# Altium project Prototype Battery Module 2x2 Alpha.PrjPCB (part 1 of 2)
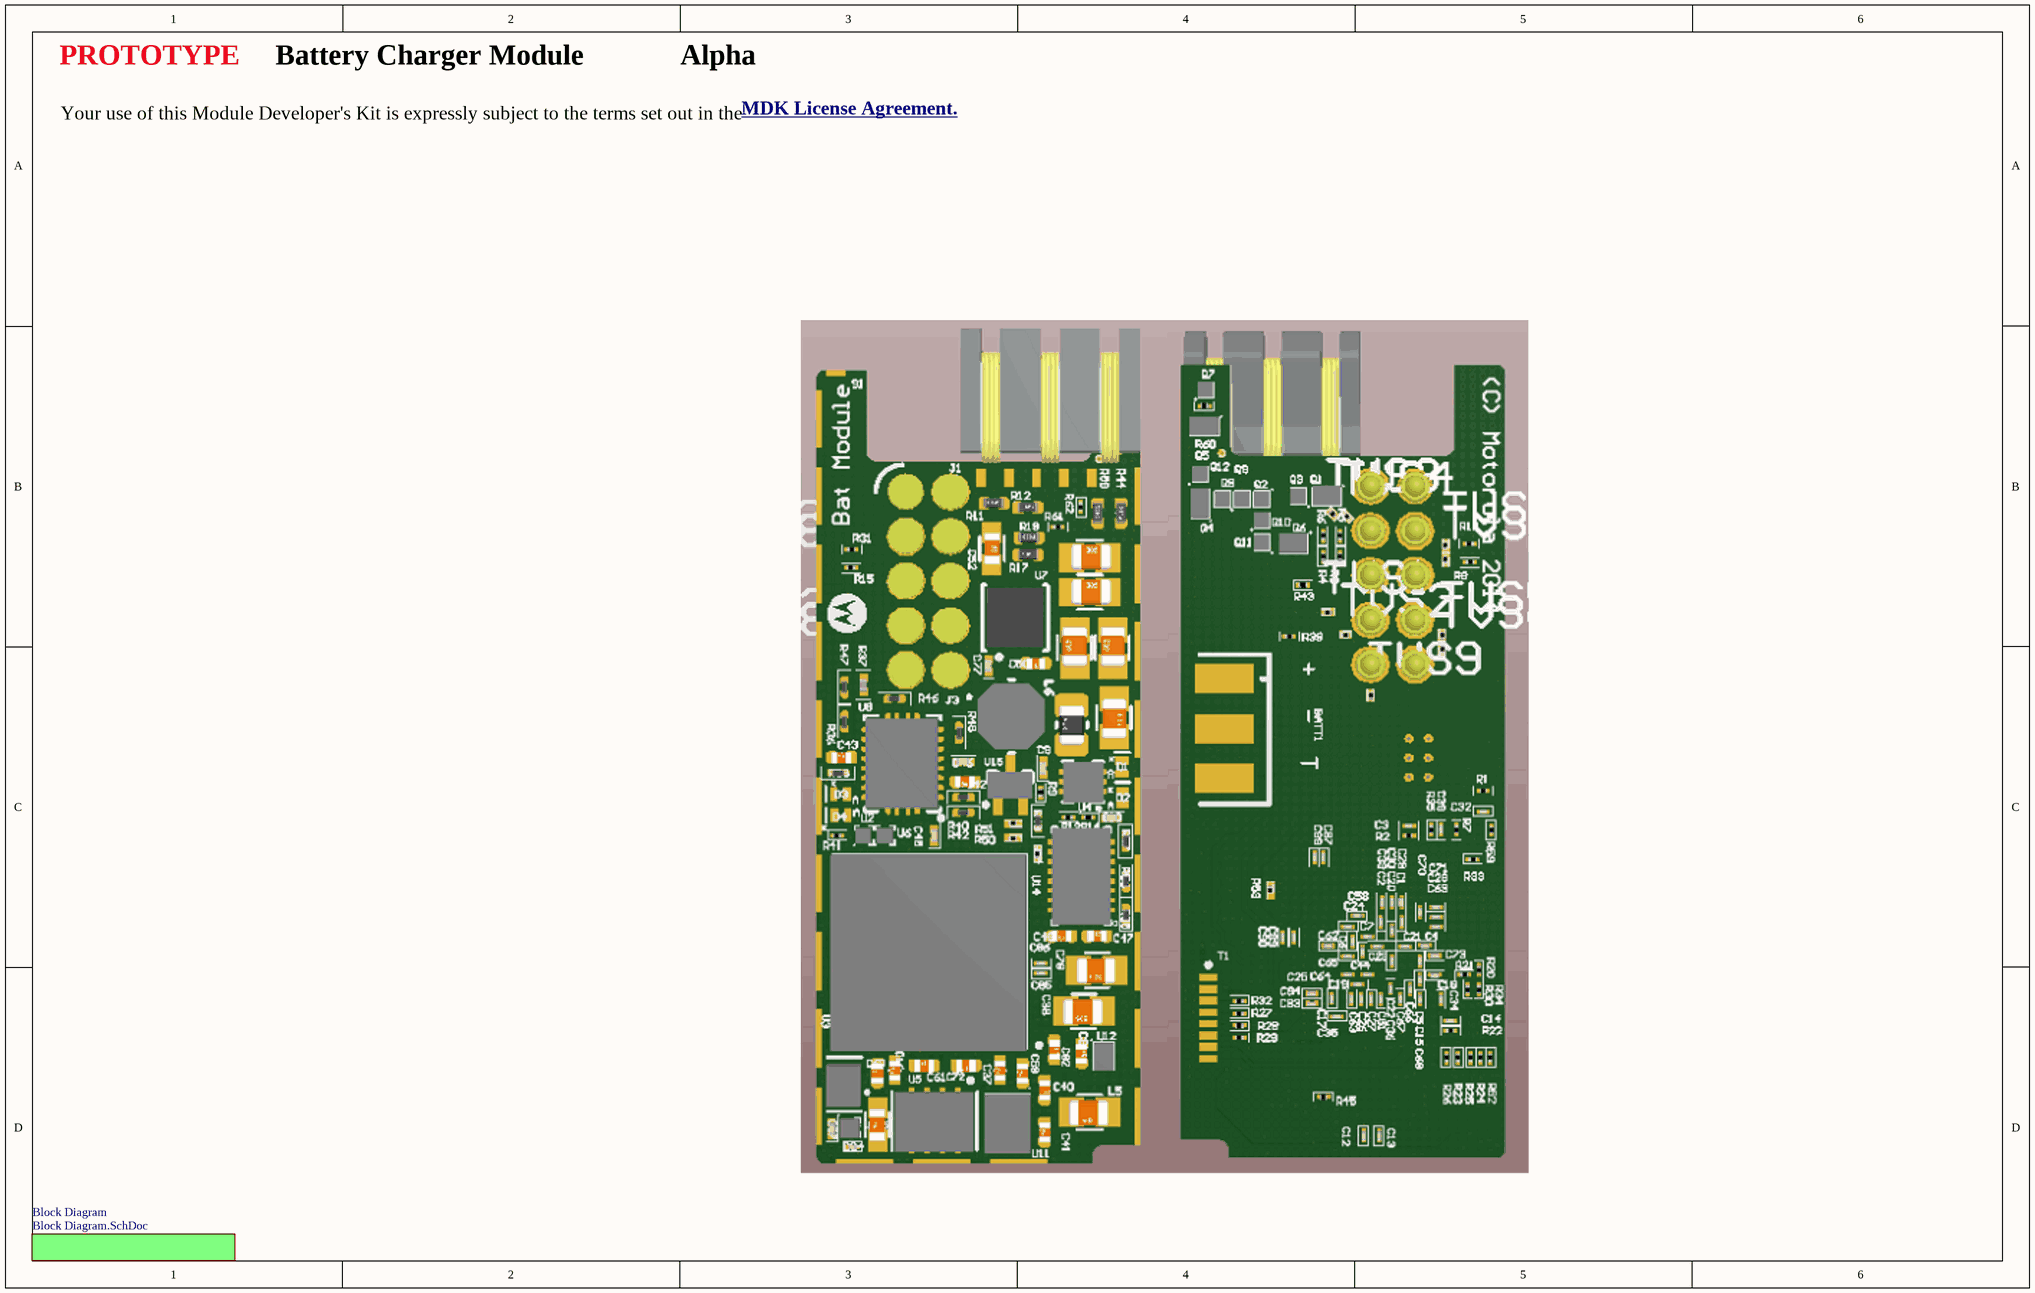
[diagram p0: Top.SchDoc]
Revision: C
12 sheets, 192 parts. Net scope: flat (ports and power ports of the same name join across sheets).
Board file: Prototype Battery Module 2x2 Alpha.PcbDoc
Sheets:
  Top.SchDoc
    Block Diagram = Block Diagram.SchDoc
      FPGA = FPGA.SchDoc
        Banks = FPGA Banks.SchDoc
        Config = FPGA Config.SchDoc
        Power = FPGA Power.SchDoc
        SERDES = FPGA SERDES.SchDoc
      Power = Power.SchDoc
      EPM = EPM.SchDoc
      HostComm = Host Comm.SchDoc
      Charger = Charger.SchDoc
      Ideal Diode = Ideal Diode.SchDoc

## Sheet Top.SchDoc: Top (License)
size B; Date: 3/12/2014; Engineer: David McCoy (Cospan Design); DocumentNumber: 1; Revision: A; SheetNumber: 1; SheetTotal: 13

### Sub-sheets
Block Diagram = Block Diagram.SchDoc: no entries

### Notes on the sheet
- PROTOTYPE
- Battery Charger Module
- Alpha
- Your use of this Module Developer's Kit is expressly subject to the terms set out in the
- MDK License Agreement. <http://www.projectara.com/mdk-license.txt>

## Sheet Block Diagram.SchDoc: Block Diagram
size B; Date: 12/18/2013; DrawnBy: David McCoy; Engineer: David McCoy (Cospan Design); DocumentNumber: 2; Revision: C; SheetNumber: 2; SheetTotal: 13
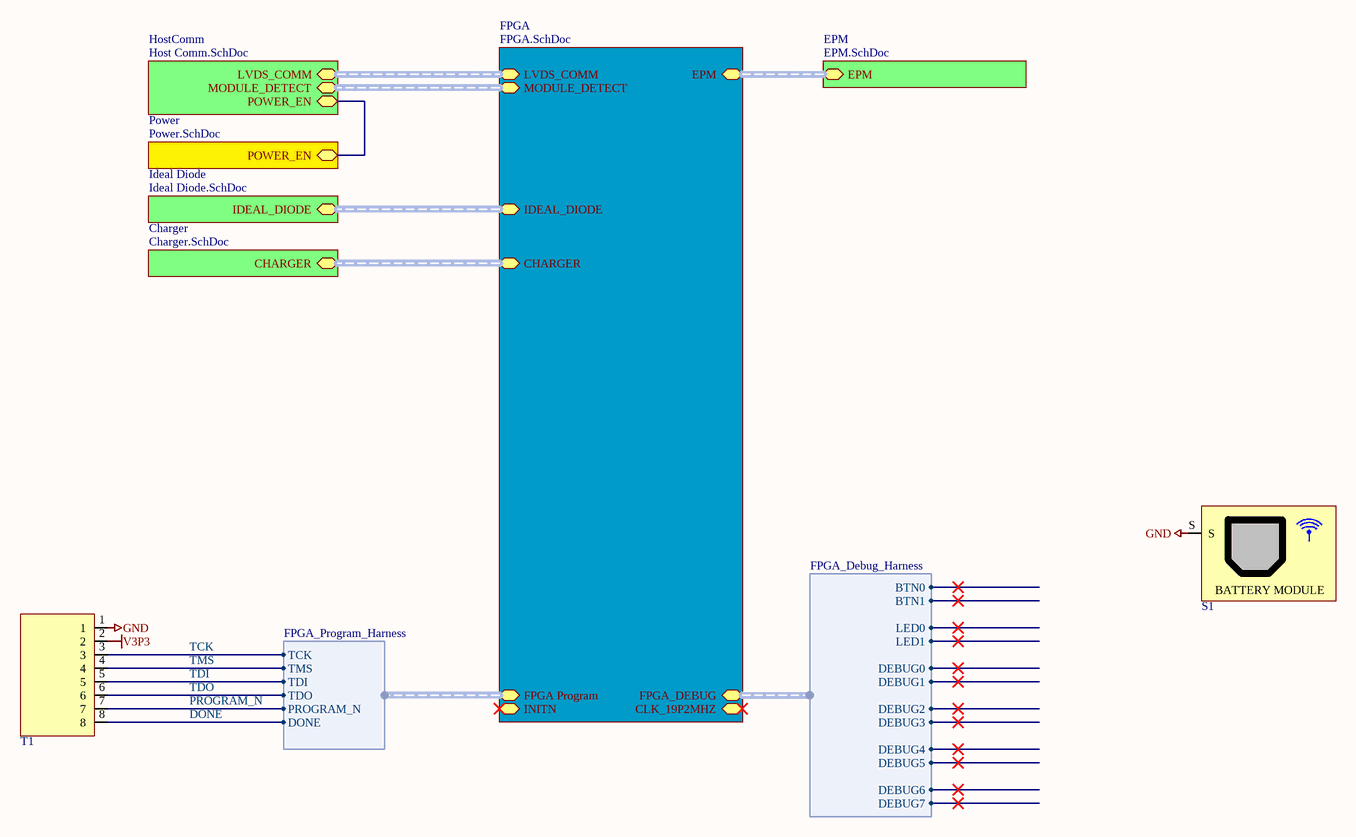
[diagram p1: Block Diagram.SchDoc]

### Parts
S1  RFSHIELD  [RFSHIELD_BATMODULE]  (value not drawn)  (no BOM)
T1  8 PIN TEST_INTERFACE  [8-PIN Test Interface]  (value not drawn)  (no BOM)

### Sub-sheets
Charger = Charger.SchDoc: CHARGER (harness Charger Harness)
EPM = EPM.SchDoc: EPM (harness EPM_Harness)
FPGA = FPGA.SchDoc: FPGA Program (harness FPGA_Program_Harness), INITN, FPGA_DEBUG (harness FPGA_Debug_Harness), CLK_19P2MHZ, EPM (harness EPM_Harness), LVDS_COMM (harness LVDS_Comm_Harness), MODULE_DETECT (harness Module_Detect_Harness), CHARGER (harness Charger Harness), IDEAL_DIODE (harness Ideal Diode Harness)
HostComm = Host Comm.SchDoc: LVDS_COMM (harness LVDS_Comm_Harness), MODULE_DETECT (harness Module_Detect_Harness), POWER_EN
Ideal Diode = Ideal Diode.SchDoc: IDEAL_DIODE (harness Ideal Diode Harness)
Power = Power.SchDoc: POWER_EN

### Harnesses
FPGA_Program_Harness: TCK, TMS, TDI, TDO, PROGRAM_N, DONE
FPGA_Debug_Harness: BTN0, BTN1, LED0, LED1, DEBUG0, DEBUG1, DEBUG2, DEBUG3, DEBUG4, DEBUG5, DEBUG6, DEBUG7

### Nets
GND: S1.S T1.1
V3P3: T1.2
DONE: T1.8 ; sheet FPGA/FPGA Program.DONE
PROGRAM_N: T1.7 ; sheet FPGA/FPGA Program.PROGRAM_N
TCK: T1.3 ; sheet FPGA/FPGA Program.TCK
TDI: T1.5 ; sheet FPGA/FPGA Program.TDI
TDO: T1.6 ; sheet FPGA/FPGA Program.TDO
TMS: T1.4 ; sheet FPGA/FPGA Program.TMS
(unnamed): sheet Power/POWER_EN, sheet HostComm/POWER_EN

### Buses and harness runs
harness sheet Charger/CHARGER = sheet FPGA/CHARGER
harness sheet EPM/EPM = sheet FPGA/EPM
harness sheet FPGA/IDEAL_DIODE = sheet Ideal Diode/IDEAL_DIODE
harness sheet FPGA/LVDS_COMM = sheet HostComm/LVDS_COMM
harness sheet FPGA/MODULE_DETECT = sheet HostComm/MODULE_DETECT

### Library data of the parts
S1 = S_RF_SHIELD_BATMODULE
T1 = TEST_INTERFACE: 8 PIN Test Interface

## Sheet FPGA.SchDoc: FPGA
size B; Date: 12/18/2013; DrawnBy: David McCoy; Engineer: David McCoy (Cospan Design); DocumentNumber: 6; Revision: C; SheetNumber: 6; SheetTotal: 13
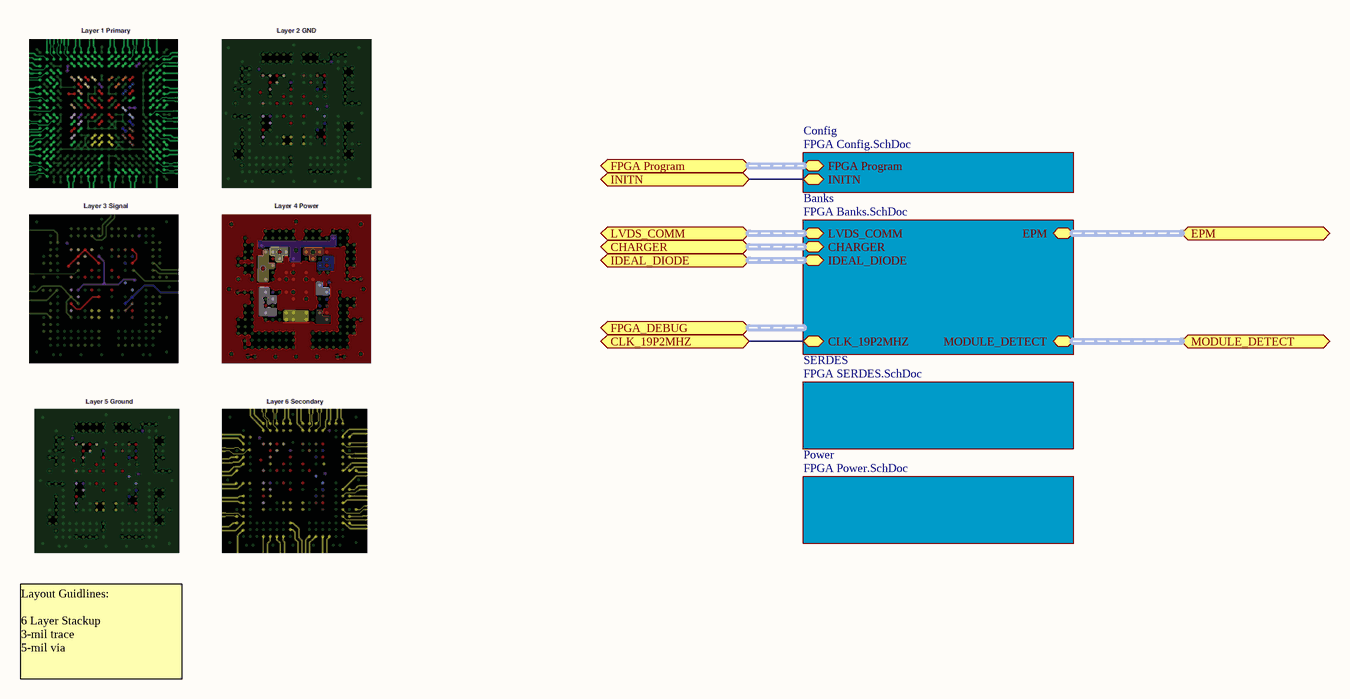
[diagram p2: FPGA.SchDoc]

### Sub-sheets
Banks = FPGA Banks.SchDoc: EPM (harness EPM_Harness), LVDS_COMM (harness LVDS_Comm_Harness), MODULE_DETECT (harness Module_Detect_Harness), CLK_19P2MHZ, CHARGER (harness Charger Harness), IDEAL_DIODE (harness Ideal Diode Harness)
Config = FPGA Config.SchDoc: FPGA Program (harness FPGA_Program_Harness), INITN
Power = FPGA Power.SchDoc: no entries
SERDES = FPGA SERDES.SchDoc: no entries

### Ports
CHARGER (harness Charger Harness), CLK_19P2MHZ, EPM (harness EPM_Harness), FPGA Program (harness FPGA_Program_Harness), FPGA_DEBUG (harness FPGA_Debug_Harness), IDEAL_DIODE (harness Ideal Diode Harness), INITN, LVDS_COMM (harness LVDS_Comm_Harness), MODULE_DETECT (harness Module_Detect_Harness)

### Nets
CLK_19P2MHZ: port CLK_19P2MHZ, sheet Banks/CLK_19P2MHZ
INITN: port INITN, sheet Config/INITN

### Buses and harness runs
harness port CHARGER = sheet Banks/CHARGER
harness port EPM = sheet Banks/EPM
harness port FPGA Program = sheet Config/FPGA Program
harness port IDEAL_DIODE = sheet Banks/IDEAL_DIODE
harness port LVDS_COMM = sheet Banks/LVDS_COMM
harness port MODULE_DETECT = sheet Banks/MODULE_DETECT

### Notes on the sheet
- Layout Guidlines:
  6 Layer Stackup
  3-mil trace
  5-mil via

## Sheet FPGA Banks.SchDoc: FPGA Banks
size B; Date: 12/18/2013; DrawnBy: David McCoy; Engineer: David McCoy (Cospan Design); DocumentNumber: 8; Revision: C; SheetNumber: 8; SheetTotal: 13
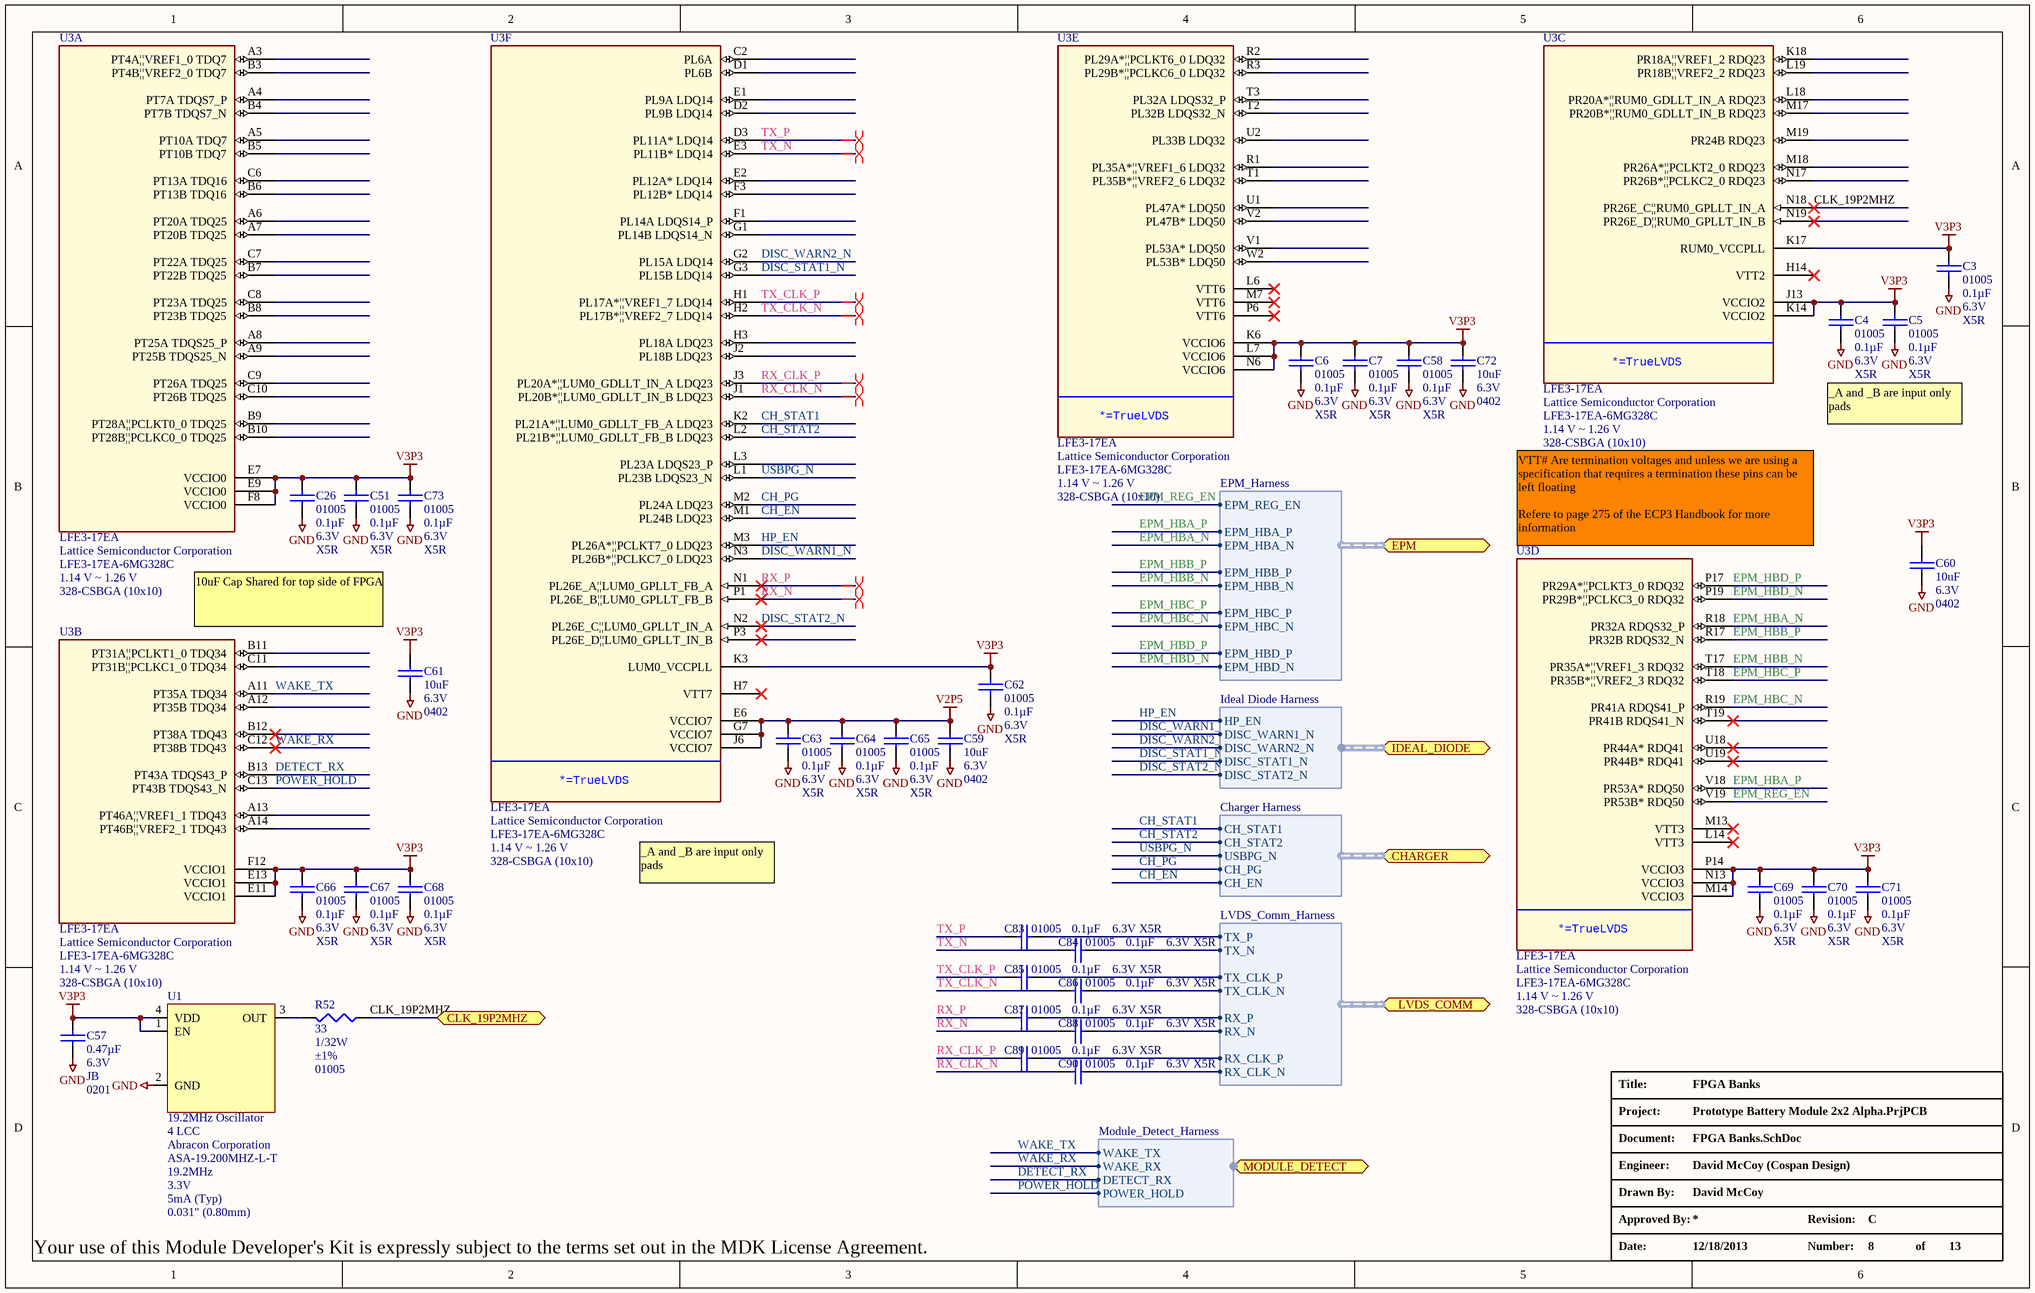
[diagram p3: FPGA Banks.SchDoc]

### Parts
C3  Package / Case: 01005  Capacitance: 0.1µF  Voltage - Rated: 6.3V  Temperature Coefficient: X5R  [C_01005]  (hidden comment: 0.1uF)
C4  Package / Case: 01005  Capacitance: 0.1µF  Voltage - Rated: 6.3V  Temperature Coefficient: X5R  [C_01005]  (hidden comment: 0.1uF)
C5  Package / Case: 01005  Capacitance: 0.1µF  Voltage - Rated: 6.3V  Temperature Coefficient: X5R  [C_01005]  (hidden comment: 0.1uF)
C6  Package / Case: 01005  Capacitance: 0.1µF  Voltage - Rated: 6.3V  Temperature Coefficient: X5R  [C_01005]  (hidden comment: 0.1uF)
C7  Package / Case: 01005  Capacitance: 0.1µF  Voltage - Rated: 6.3V  Temperature Coefficient: X5R  [C_01005]  (hidden comment: 0.1uF)
C26  Package / Case: 01005  Capacitance: 0.1µF  Voltage - Rated: 6.3V  Temperature Coefficient: X5R  [C_01005]  (hidden comment: 0.1uF)
C51  Package / Case: 01005  Capacitance: 0.1µF  Voltage - Rated: 6.3V  Temperature Coefficient: X5R  [C_01005]  (hidden comment: 0.1uF)
C57  Voltage - Rated: 6.3V  Temperature Coefficient: JB  Package / Case: 0201  [CAPC0201]  (hidden comment: 0.47µF)
C58  Package / Case: 01005  Capacitance: 0.1µF  Voltage - Rated: 6.3V  Temperature Coefficient: X5R  [C_01005]  (hidden comment: 0.1uF)
C59  Voltage - Rated: 6.3V  Package / Case: 0402  [C_0402]  (hidden comment: 10uF)
C60  Voltage - Rated: 6.3V  Package / Case: 0402  [C_0402]  (hidden comment: 10uF)
C61  Voltage - Rated: 6.3V  Package / Case: 0402  [C_0402]  (hidden comment: 10uF)
C62  Package / Case: 01005  Capacitance: 0.1µF  Voltage - Rated: 6.3V  Temperature Coefficient: X5R  [C_01005]  (hidden comment: 0.1uF)
C63  Package / Case: 01005  Capacitance: 0.1µF  Voltage - Rated: 6.3V  Temperature Coefficient: X5R  [C_01005]  (hidden comment: 0.1uF)
C64  Package / Case: 01005  Capacitance: 0.1µF  Voltage - Rated: 6.3V  Temperature Coefficient: X5R  [C_01005]  (hidden comment: 0.1uF)
C65  Package / Case: 01005  Capacitance: 0.1µF  Voltage - Rated: 6.3V  Temperature Coefficient: X5R  [C_01005]  (hidden comment: 0.1uF)
C66  Package / Case: 01005  Capacitance: 0.1µF  Voltage - Rated: 6.3V  Temperature Coefficient: X5R  [C_01005]  (hidden comment: 0.1uF)
C67  Package / Case: 01005  Capacitance: 0.1µF  Voltage - Rated: 6.3V  Temperature Coefficient: X5R  [C_01005]  (hidden comment: 0.1uF)
C68  Package / Case: 01005  Capacitance: 0.1µF  Voltage - Rated: 6.3V  Temperature Coefficient: X5R  [C_01005]  (hidden comment: 0.1uF)
C69  Package / Case: 01005  Capacitance: 0.1µF  Voltage - Rated: 6.3V  Temperature Coefficient: X5R  [C_01005]  (hidden comment: 0.1uF)
C70  Package / Case: 01005  Capacitance: 0.1µF  Voltage - Rated: 6.3V  Temperature Coefficient: X5R  [C_01005]  (hidden comment: 0.1uF)
C71  Package / Case: 01005  Capacitance: 0.1µF  Voltage - Rated: 6.3V  Temperature Coefficient: X5R  [C_01005]  (hidden comment: 0.1uF)
C72  Voltage - Rated: 6.3V  Package / Case: 0402  [C_0402]  (hidden comment: 10uF)
C73  Package / Case: 01005  Capacitance: 0.1µF  Voltage - Rated: 6.3V  Temperature Coefficient: X5R  [C_01005]  (hidden comment: 0.1uF)
C83  Package / Case: 01005  Capacitance: 0.1µF  Voltage - Rated: 6.3V  Temperature Coefficient: X5R  [C_01005]  (hidden comment: 0.1uF)
C84  Package / Case: 01005  Capacitance: 0.1µF  Voltage - Rated: 6.3V  Temperature Coefficient: X5R  [C_01005]  (hidden comment: 0.1uF)
C85  Package / Case: 01005  Capacitance: 0.1µF  Voltage - Rated: 6.3V  Temperature Coefficient: X5R  [C_01005]  (hidden comment: 0.1uF)
C86  Package / Case: 01005  Capacitance: 0.1µF  Voltage - Rated: 6.3V  Temperature Coefficient: X5R  [C_01005]  (hidden comment: 0.1uF)
C87  Package / Case: 01005  Capacitance: 0.1µF  Voltage - Rated: 6.3V  Temperature Coefficient: X5R  [C_01005]  (hidden comment: 0.1uF)
C88  Package / Case: 01005  Capacitance: 0.1µF  Voltage - Rated: 6.3V  Temperature Coefficient: X5R  [C_01005]  (hidden comment: 0.1uF)
C89  Package / Case: 01005  Capacitance: 0.1µF  Voltage - Rated: 6.3V  Temperature Coefficient: X5R  [C_01005]  (hidden comment: 0.1uF)
C90  Package / Case: 01005  Capacitance: 0.1µF  Voltage - Rated: 6.3V  Temperature Coefficient: X5R  [C_01005]  (hidden comment: 0.1uF)
R52  Power (Watts): 1/32W  Tolerance: ±1%  Case: 01005  [R_01005]  (hidden comment: 33)
U1  19.2MHz Oscillator  Package / Case: 4 LCC  Manufacturer: Abracon Corporation  Manufacturer Part Number: ASA-19.200MHZ-L-T  Frequency: 19.2MHz  Voltage - Supply: 3.3V  Current - Supply (Max): 5mA (Typ)  Height: 0.031" (0.80mm)  [LCCS165P160X200X70-4N]
U3  LFE3-17EA  Manufacturer: Lattice Semiconductor Corporation  Manufacturer Part Number: LFE3-17EA-6MG328C  Voltage - Supply: 1.14 V ~ 1.26 V  Supplier Device Package: 328-CSBGA (10x10)  [BGA328C50P19X19_1000X1000X150]  (parts A,B,C,D,E,F of 10)

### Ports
CHARGER (harness Charger Harness), CLK_19P2MHZ, EPM (harness EPM_Harness), IDEAL_DIODE (harness Ideal Diode Harness), LVDS_COMM (harness LVDS_Comm_Harness), MODULE_DETECT (harness Module_Detect_Harness)

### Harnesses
LVDS_Comm_Harness: TX_P, TX_N, TX_CLK_P, TX_CLK_N, RX_P, RX_N, RX_CLK_P, RX_CLK_N
Charger Harness: CH_STAT1, CH_STAT2, USBPG_N, CH_PG, CH_EN
Ideal Diode Harness: HP_EN, DISC_WARN1_N, DISC_WARN2_N, DISC_STAT1_N, DISC_STAT2_N
EPM_Harness: EPM_REG_EN, EPM_HBA_P, EPM_HBA_N, EPM_HBB_P, EPM_HBB_N, EPM_HBC_P, EPM_HBC_N, EPM_HBD_P, EPM_HBD_N
Module_Detect_Harness: WAKE_TX, WAKE_RX, DETECT_RX, POWER_HOLD

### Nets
GND: C3.1 C4.1 C5.1 C6.1 C7.1 C26.1 C51.1 C57.1 C58.1 C59.1 C60.1 C61.1 C62.1 C63.1 C64.1 C65.1 C66.1 C67.1 C68.1 C69.1 C70.1 C71.1 C72.1 C73.1 U1.2(GND)
V2P5: C59.2 C63.2 C64.2 C65.2 U3.E6(VCCIO7) U3.G7(VCCIO7) U3.J6(VCCIO7)
V3P3: C3.2 C4.2 C5.2 C6.2 C7.2 C26.2 C51.2 C57.2 C58.2 C60.2 C61.2 C62.2 C66.2 C67.2 C68.2 C69.2 C70.2 C71.2 C72.2 C73.2 U1.1(EN) U1.4(VDD) U3.E7(VCCIO0) U3.E9(VCCIO0) U3.E11(VCCIO1) U3.E13(VCCIO1) U3.F8(VCCIO0) U3.F12(VCCIO1) U3.J13(VCCIO2) U3.K3(LUM0_VCCPLL) U3.K6(VCCIO6) U3.K14(VCCIO2) U3.K17(RUM0_VCCPLL) U3.L7(VCCIO6) U3.M14(VCCIO3) U3.N6(VCCIO6) U3.N13(VCCIO3) U3.P14(VCCIO3)
C_RX_CLK_N: C90.1 ; port LVDS_COMM.RX_CLK_N
C_RX_CLK_P: C89.1 ; port LVDS_COMM.RX_CLK_P
C_RX_N: C88.1 ; port LVDS_COMM.RX_N
C_RX_P: C87.1 ; port LVDS_COMM.RX_P
C_TX_CLK_N: C86.1 ; port LVDS_COMM.TX_CLK_N
C_TX_CLK_P: C85.1 ; port LVDS_COMM.TX_CLK_P
C_TX_N: C84.1 ; port LVDS_COMM.TX_N
C_TX_P: C83.1 ; port LVDS_COMM.TX_P
CH_EN: U3.M1(PL24B_LDQ23) ; port CHARGER.CH_EN
CH_PG: U3.M2(PL24A_LDQ23) ; port CHARGER.CH_PG
CH_STAT1: U3.K2(PL21A*¦¦LUM0_GDLLT_FB_A_LDQ23) ; port CHARGER.CH_STAT1
CH_STAT2: U3.L2(PL21B*¦¦LUM0_GDLLT_FB_B_LDQ23) ; port CHARGER.CH_STAT2
CLK_19P2MHZ: R52.2 U3.N18(PR26E_C¦¦RUM0_GPLLT_IN_A) ; port CLK_19P2MHZ
DETECT_RX: U3.B13(PT43A_TDQS43_P) ; port MODULE_DETECT.DETECT_RX
DISC_STAT1_N: U3.G3(PL15B_LDQ14) ; port IDEAL_DIODE.DISC_STAT1_N
DISC_STAT2_N: U3.N2(PL26E_C¦¦LUM0_GPLLT_IN_A) ; port IDEAL_DIODE.DISC_STAT2_N
DISC_WARN1_N: U3.N3(PL26B*¦¦PCLKC7_0_LDQ23) ; port IDEAL_DIODE.DISC_WARN1_N
DISC_WARN2_N: U3.G2(PL15A_LDQ14) ; port IDEAL_DIODE.DISC_WARN2_N
EPM_HBA_N: U3.R18(PR32A_RDQS32_P) ; port EPM.EPM_HBA_N
EPM_HBA_P: U3.V18(PR53A*_RDQ50) ; port EPM.EPM_HBA_P
EPM_HBB_N: U3.T17(PR35A*¦¦VREF1_3_RDQ32) ; port EPM.EPM_HBB_N
EPM_HBB_P: U3.R17(PR32B_RDQS32_N) ; port EPM.EPM_HBB_P
EPM_HBC_N: U3.R19(PR41A_RDQS41_P) ; port EPM.EPM_HBC_N
EPM_HBC_P: U3.T18(PR35B*¦¦VREF2_3_RDQ32) ; port EPM.EPM_HBC_P
EPM_HBD_N: U3.P19(PR29B*¦¦PCLKC3_0_RDQ32) ; port EPM.EPM_HBD_N
EPM_HBD_P: U3.P17(PR29A*¦¦PCLKT3_0_RDQ32) ; port EPM.EPM_HBD_P
EPM_REG_EN: U3.V19(PR53B*_RDQ50) ; port EPM.EPM_REG_EN
HP_EN: U3.M3(PL26A*¦¦PCLKT7_0_LDQ23) ; port IDEAL_DIODE.HP_EN
POWER_HOLD: U3.C13(PT43B_TDQS43_N) ; port MODULE_DETECT.POWER_HOLD
RX_CLK_N: C90.2 U3.J1(PL20B*¦¦LUM0_GDLLT_IN_B_LDQ23)
RX_CLK_P: C89.2 U3.J3(PL20A*¦¦LUM0_GDLLT_IN_A_LDQ23)
RX_N: C88.2 U3.P1(PL26E_B¦¦LUM0_GPLLT_FB_B)
RX_P: C87.2 U3.N1(PL26E_A¦¦LUM0_GPLLT_FB_A)
TX_CLK_N: C86.2 U3.H2(PL17B*¦¦VREF2_7_LDQ14)
TX_CLK_P: C85.2 U3.H1(PL17A*¦¦VREF1_7_LDQ14)
TX_N: C84.2 U3.E3(PL11B*_LDQ14)
TX_P: C83.2 U3.D3(PL11A*_LDQ14)
USBPG_N: U3.L1(PL23B_LDQS23_N) ; port CHARGER.USBPG_N
WAKE_RX: U3.C12(PT38B_TDQ43) ; port MODULE_DETECT.WAKE_RX
WAKE_TX: U3.A11(PT35A_TDQ34) ; port MODULE_DETECT.WAKE_TX
NetR52_1: R52.1 U1.3(OUT)

Not connected (* = marked no-connect by the designer): U3 A3(PT4A¦¦VREF1_0_TDQ7) A4(PT7A_TDQS7_P) A5(PT10A_TDQ7) A6(PT20A_TDQ25) A7(PT20B_TDQ25) A8(PT25A_TDQS25_P) A9(PT25B_TDQS25_N) A12(PT35B_TDQ34) A13(PT46A¦¦VREF1_1_TDQ43) A14(PT46B¦¦VREF2_1_TDQ43) B3(PT4B¦¦VREF2_0_TDQ7) B4(PT7B_TDQS7_N) B5(PT10B_TDQ7) B6(PT13B_TDQ16) B7(PT22B_TDQ25) B8(PT23B_TDQ25) B9(PT28A¦¦PCLKT0_0_TDQ25) B10(PT28B¦¦PCLKC0_0_TDQ25) B11(PT31A¦¦PCLKT1_0_TDQ34) B12(PT38A_TDQ43)* C2(PL6A) C6(PT13A_TDQ16) C7(PT22A_TDQ25) C8(PT23A_TDQ25) C9(PT26A_TDQ25) C10(PT26B_TDQ25) C11(PT31B¦¦PCLKC1_0_TDQ34) D1(PL6B) D2(PL9B_LDQ14) E1(PL9A_LDQ14) E2(PL12A*_LDQ14) F1(PL14A_LDQS14_P) F3(PL12B*_LDQ14) G1(PL14B_LDQS14_N) H3(PL18A_LDQ23) H7(VTT7)* H14(VTT2)* J2(PL18B_LDQ23) K18(PR18A¦¦VREF1_2_RDQ23) L3(PL23A_LDQS23_P) L6(VTT6)* L14(VTT3)* L18(PR20A*¦¦RUM0_GDLLT_IN_A_RDQ23) L19(PR18B¦¦VREF2_2_RDQ23) M7(VTT6)* M13(VTT3)* M17(PR20B*¦¦RUM0_GDLLT_IN_B_RDQ23) M18(PR26A*¦¦PCLKT2_0_RDQ23) M19(PR24B_RDQ23) N17(PR26B*¦¦PCLKC2_0_RDQ23) N19(PR26E_D¦¦RUM0_GPLLT_IN_B)* P3(PL26E_D¦¦LUM0_GPLLT_IN_B)* P6(VTT6)* R1(PL35A*¦¦VREF1_6_LDQ32) R2(PL29A*¦¦PCLKT6_0_LDQ32) R3(PL29B*¦¦PCLKC6_0_LDQ32) T1(PL35B*¦¦VREF2_6_LDQ32) T2(PL32B_LDQS32_N) T3(PL32A_LDQS32_P) T19(PR41B_RDQS41_N)* U1(PL47A*_LDQ50) U2(PL33B_LDQ32) U18(PR44A*_RDQ41)* U19(PR44B*_RDQ41)* V1(PL53A*_LDQ50) V2(PL47B*_LDQ50) W2(PL53B*_LDQ50)

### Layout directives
differential pair: RX_CLK_N, RX_CLK_P, RX_N, RX_P, TX_CLK_N, TX_CLK_P, TX_N, TX_P

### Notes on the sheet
- _A and _B are input only pads
- (near U3) VTT# Are termination voltages and unless we are using a specification that requires a termination these pins can be left floating
  Refere to page 275 of the ECP3 Handbook for more information
- (near U3) 10uF Cap Shared for top side of FPGA

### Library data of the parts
C3-C7 C26 C51 C58 C62-C71 C73 C83-C90 = C_01005_0.1uF: CAP CER 0.1UF 6.3V 20% X5R 01005; Manufacturer: TDK Corporation; Manufacturer Part Number: C0402X5R0J104M020BC
C57 = C_0201_0.47µF: CAP CER 0.47UF 6.3V 20% JB 0201; Manufacturer: TDK Corporation; Manufacturer Part Number: C0603JB0J474M030BC
C59-C61 C72 = C_0402_10uF: CAP CER 10UF 4V 20% X5R 0402; Manufacturer: Taiyo Yuden; Manufacturer Part Number: AMK105CBJ106MV-F
R52 = R_01005_33: RES 33 OHM 1/32W 1% 01005; Manufacturer: Samsung Electro-Mechanics America, Inc; Manufacturer Part Number: RC0402F330CS; Temperature Coefficient: ±300ppm/°C
U1 = U_ASA-19.200MHZ-L-T: OSC 19.200 MHZ 3.3V SMD; Function: Tri-State (Output Enable); Output: HCMOS, TTL; Frequency Stability: ±50ppm
U3 = U_LFE3-17EA-MG328: IC FPGA 17KLUTS 116I/O 328-BGA; SPLIT_INST: TRUE; SWAP_INFO: (S1+S2+S3+S4+S5+S6+S7+S8+S9+S10); Number of LABs/CLBs: 2125; Number of Logic Elements/Cells: 17000; Total RAM Bits: 716800; Number of I /O: 116

## Sheet FPGA Config.SchDoc: FPGA Config
size B; Date: 12/18/2013; DrawnBy: David McCoy; Engineer: David McCoy (Cospan Design); DocumentNumber: 7; Revision: C; SheetNumber: 7; SheetTotal: 13
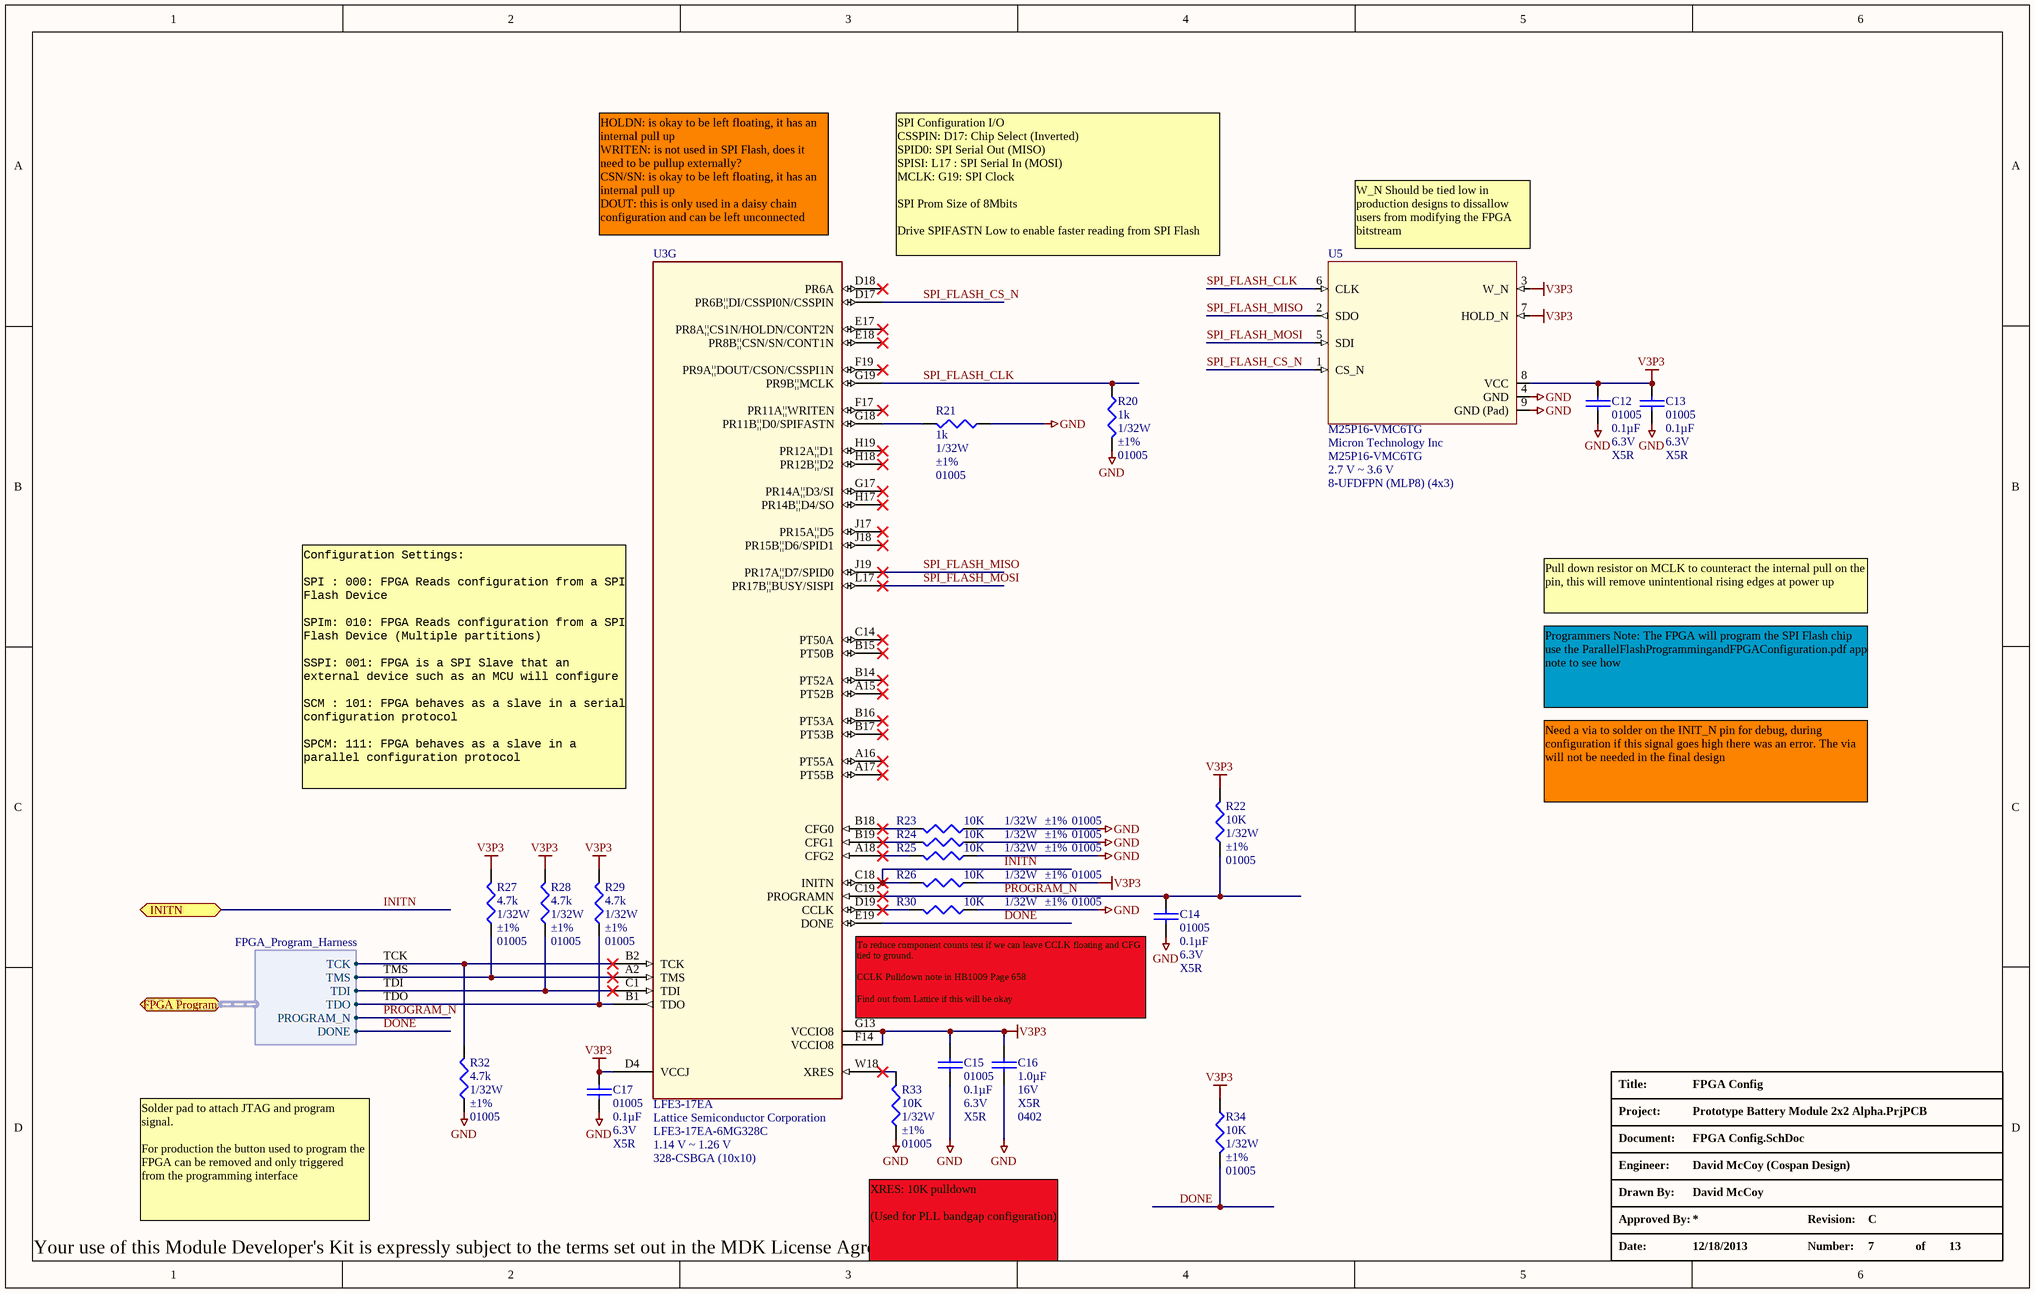
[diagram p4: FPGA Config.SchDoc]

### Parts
C12  Package / Case: 01005  Capacitance: 0.1µF  Voltage - Rated: 6.3V  Temperature Coefficient: X5R  [C_01005]  (hidden comment: 0.1uF)
C13  Package / Case: 01005  Capacitance: 0.1µF  Voltage - Rated: 6.3V  Temperature Coefficient: X5R  [C_01005]  (hidden comment: 0.1uF)
C14  Package / Case: 01005  Capacitance: 0.1µF  Voltage - Rated: 6.3V  Temperature Coefficient: X5R  [C_01005]  (hidden comment: 0.1uF)
C15  Package / Case: 01005  Capacitance: 0.1µF  Voltage - Rated: 6.3V  Temperature Coefficient: X5R  [C_01005]  (hidden comment: 0.1uF)
C16  Capacitance: 1.0µF  Voltage - Rated: 16V  Temperature Coefficient: X5R  Package / Case: 0402  [C_ERA-0402]  (hidden comment: 1.0uF)
C17  Package / Case: 01005  Capacitance: 0.1µF  Voltage - Rated: 6.3V  Temperature Coefficient: X5R  [C_01005]  (hidden comment: 0.1uF)
R20  Power (Watts): 1/32W  Tolerance: ±1%  Case: 01005  [R_01005]  (hidden comment: 1k)
R21  Power (Watts): 1/32W  Tolerance: ±1%  Case: 01005  [R_01005]  (hidden comment: 1k)
R22  Power (Watts): 1/32W  Tolerance: ±1%  Case: 01005  [R_01005]  (hidden comment: 10K)
R23  Power (Watts): 1/32W  Tolerance: ±1%  Case: 01005  [R_01005]  (hidden comment: 10K)
R24  Power (Watts): 1/32W  Tolerance: ±1%  Case: 01005  [R_01005]  (hidden comment: 10K)
R25  Power (Watts): 1/32W  Tolerance: ±1%  Case: 01005  [R_01005]  (hidden comment: 10K)
R26  Power (Watts): 1/32W  Tolerance: ±1%  Case: 01005  [R_01005]  (hidden comment: 10K)
R27  Power (Watts): 1/32W  Tolerance: ±1%  Case: 01005  [R_01005]  (hidden comment: 4.7k)
R28  Power (Watts): 1/32W  Tolerance: ±1%  Case: 01005  [R_01005]  (hidden comment: 4.7k)
R29  Power (Watts): 1/32W  Tolerance: ±1%  Case: 01005  [R_01005]  (hidden comment: 4.7k)
R30  Power (Watts): 1/32W  Tolerance: ±1%  Case: 01005  [R_01005]  (hidden comment: 10K)
R32  Power (Watts): 1/32W  Tolerance: ±1%  Case: 01005  [R_01005]  (hidden comment: 4.7k)
R33  Power (Watts): 1/32W  Tolerance: ±1%  Case: 01005  [R_01005]  (hidden comment: 10K)
R34  Power (Watts): 1/32W  Tolerance: ±1%  Case: 01005  [R_01005]  (hidden comment: 10K)
U3  LFE3-17EA  Manufacturer: Lattice Semiconductor Corporation  Manufacturer Part Number: LFE3-17EA-6MG328C  Voltage - Supply: 1.14 V ~ 1.26 V  Supplier Device Package: 328-CSBGA (10x10)  [BGA328C50P19X19_1000X1000X150]  (part G of 10)
U5  M25P16-VMC6TG  Manufacturer: Micron Technology Inc  Voltage - Supply: 2.7 V ~ 3.6 V  Supplier Device Package: 8-UFDFPN (MLP8) (4x3)  [UFDFN8]

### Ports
FPGA Program (harness FPGA_Program_Harness), INITN

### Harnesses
FPGA_Program_Harness: TCK, TMS, TDI, TDO, PROGRAM_N, DONE

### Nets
GND: C12.2 C13.2 C14.2 C15.2 C16.1 C17.2 R20.1 R21.2 R23.2 R24.2 R25.2 R30.2 R32.2 R33.2 U5.4(GND) U5.9(GND_(Pad))
V3P3: C12.1 C13.1 C15.1 C16.2 C17.1 R22.1 R26.2 R27.1 R28.1 R29.1 R34.2 U3.D4(VCCJ) U3.F14(VCCIO8) U3.G13(VCCIO8) U5.3(W_N) U5.7(HOLD_N) U5.8(VCC)
DONE: R34.1 U3.E19(DONE) ; port FPGA Program.DONE
INITN: R26.1 U3.C18(INITN) ; port INITN
PROGRAM_N: C14.1 R22.2 U3.C19(PROGRAMN) ; port FPGA Program.PROGRAM_N
SPI_FLASH_CLK: R20.2 U3.G19(PR9B¦¦MCLK) U5.6(CLK)
SPI_FLASH_CS_N: U3.D17(PR6B¦¦DI/CSSPI0N/CSSPIN) U5.1(CS_N)
SPI_FLASH_MISO: U3.J19(PR17A¦¦D7/SPID0) U5.2(SDO)
SPI_FLASH_MOSI: U3.L17(PR17B¦¦BUSY/SISPI) U5.5(SDI)
TCK: R32.1 U3.B2(TCK) ; port FPGA Program.TCK
TDI: R28.2 U3.C1(TDI) ; port FPGA Program.TDI
TDO: R29.2 U3.B1(TDO) ; port FPGA Program.TDO
TMS: R27.2 U3.A2(TMS) ; port FPGA Program.TMS
NetR21_1: R21.1 U3.G18(PR11B¦¦D0/SPIFASTN)
NetR23_1: R23.1 U3.B18(CFG0)
NetR24_1: R24.1 U3.B19(CFG1)
NetR25_1: R25.1 U3.A18(CFG2)
NetR30_1: R30.1 U3.D19(CCLK)
NetR33_1: R33.1 U3.W18(XRES)

Not connected (* = marked no-connect by the designer): U3 A15(PT52B)* A16(PT55A)* A17(PT55B)* B14(PT52A)* B15(PT50B)* B16(PT53A)* B17(PT53B)* C14(PT50A)* D18(PR6A)* E17(PR8A¦¦CS1N/HOLDN/CONT2N)* E18(PR8B¦¦CSN/SN/CONT1N)* F17(PR11A¦¦WRITEN)* F19(PR9A¦¦DOUT/CSON/CSSPI1N)* G17(PR14A¦¦D3/SI)* H17(PR14B¦¦D4/SO)* H18(PR12B¦¦D2)* H19(PR12A¦¦D1)* J17(PR15A¦¦D5)* J18(PR15B¦¦D6/SPID1)*

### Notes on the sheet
- HOLDN: is okay to be left floating, it has an internal pull up
  WRITEN: is not used in SPI Flash, does it need to be pullup externally?
  CSN/SN: is okay to be left floating, it has an internal pull up
  DOUT: this is only used in a daisy chain configuration and can be left unconnected
- SPI Configuration I/O
  CSSPIN: D17: Chip Select (Inverted)
  SPID0: SPI Serial Out (MISO)
  SPISI: L17 : SPI Serial In (MOSI)
  MCLK: G19: SPI Clock
  SPI Prom Size of 8Mbits
  Drive SPIFASTN Low to enable faster reading from SPI Flash
- (near U5) W_N Should be tied low in production designs to dissallow users from modifying the FPGA bitstream
- Pull down resistor on MCLK to counteract the internal pull on the pin, this will remove unintentional rising edges at power up
- Programmers Note: The FPGA will program the SPI Flash chip use the ParallelFlashProgrammingandFPGAConfiguration.pdf app note to see how
- (near U3) Configuration Settings:
  SPI : 000: FPGA Reads configuration from a SPI Flash Device
  SPIm: 010: FPGA Reads configuration from a SPI Flash Device (Multiple partitions)
  SSPI: 001: FPGA is a SPI Slave that an external device such as an MCU will configure
  SCM : 101: FPGA behaves as a slave in a serial configuration protocol
  SPCM: 111: FPGA behaves as a slave in a parallel configuration protocol
- Need a via to solder on the INIT_N pin for debug, during configuration if this signal goes high there was an error. The via will not be needed in the final design
- (near U3) To reduce component counts test if we can leave CCLK floating and CFG tied to ground.
  CCLK Pulldown note in HB1009 Page 658
  Find out from Lattice if this will be okay
- Solder pad to attach JTAG and program signal.
  For production the button used to program the FPGA can be removed and only triggered from the programming interface
- XRES: 10K pulldown
  (Used for PLL bandgap configuration)

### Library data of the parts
C12-C15 C17 = C_01005_0.1uF: as C3 on sheet FPGA Banks
C16 = C_0402_1.0UF_16V: CAP CER 1.0UF 16V X5R 0402; Manufacturer: TDK Corporation; Manufacturer Part Number: C1005X5R1C105K; Tolerance: ±10%
R20 R21 = R_01005_1k: RES 1K OHM 1/32W 1% 01005 SM; Manufacturer: Panasonic Electronic Components; Manufacturer Part Number: ERJ-XGNF1001Y; Temperature Coefficient: ±200ppm/°C
R22-R26 R30 R33 R34 = R_01005_10K: RES 10K OHM 1/32W 1% 01005; Manufacturer: Samsung Electro-Mechanics America, Inc; Manufacturer Part Number: RC0402F103CS; Temperature Coefficient: ±250ppm/°C
R27-R29 R32 = R_01005_4.7k: RES 4.7K OHM 1/32W 1% 01005 SMD; Manufacturer: Yageo; Manufacturer Part Number: RC0100FR-074K7L; Temperature Coefficient: ±250ppm/°C
U3 = U_LFE3-17EA-MG328: as U3 on sheet FPGA Banks
U5 = U_M25P16-VMC6TG: IC FLASH 16MBIT 75MHZ 8UFDFPN; Memory Type: FLASH - NOR; Memory Size: 16M (2M x 8); Interface: SPI Serial

## Sheet FPGA Power.SchDoc: FPGA Power
size B; Date: 12/18/2013; DrawnBy: David McCoy; Engineer: David McCoy (Cospan Design); DocumentNumber: 11; Revision: C; SheetNumber: 11; SheetTotal: 13
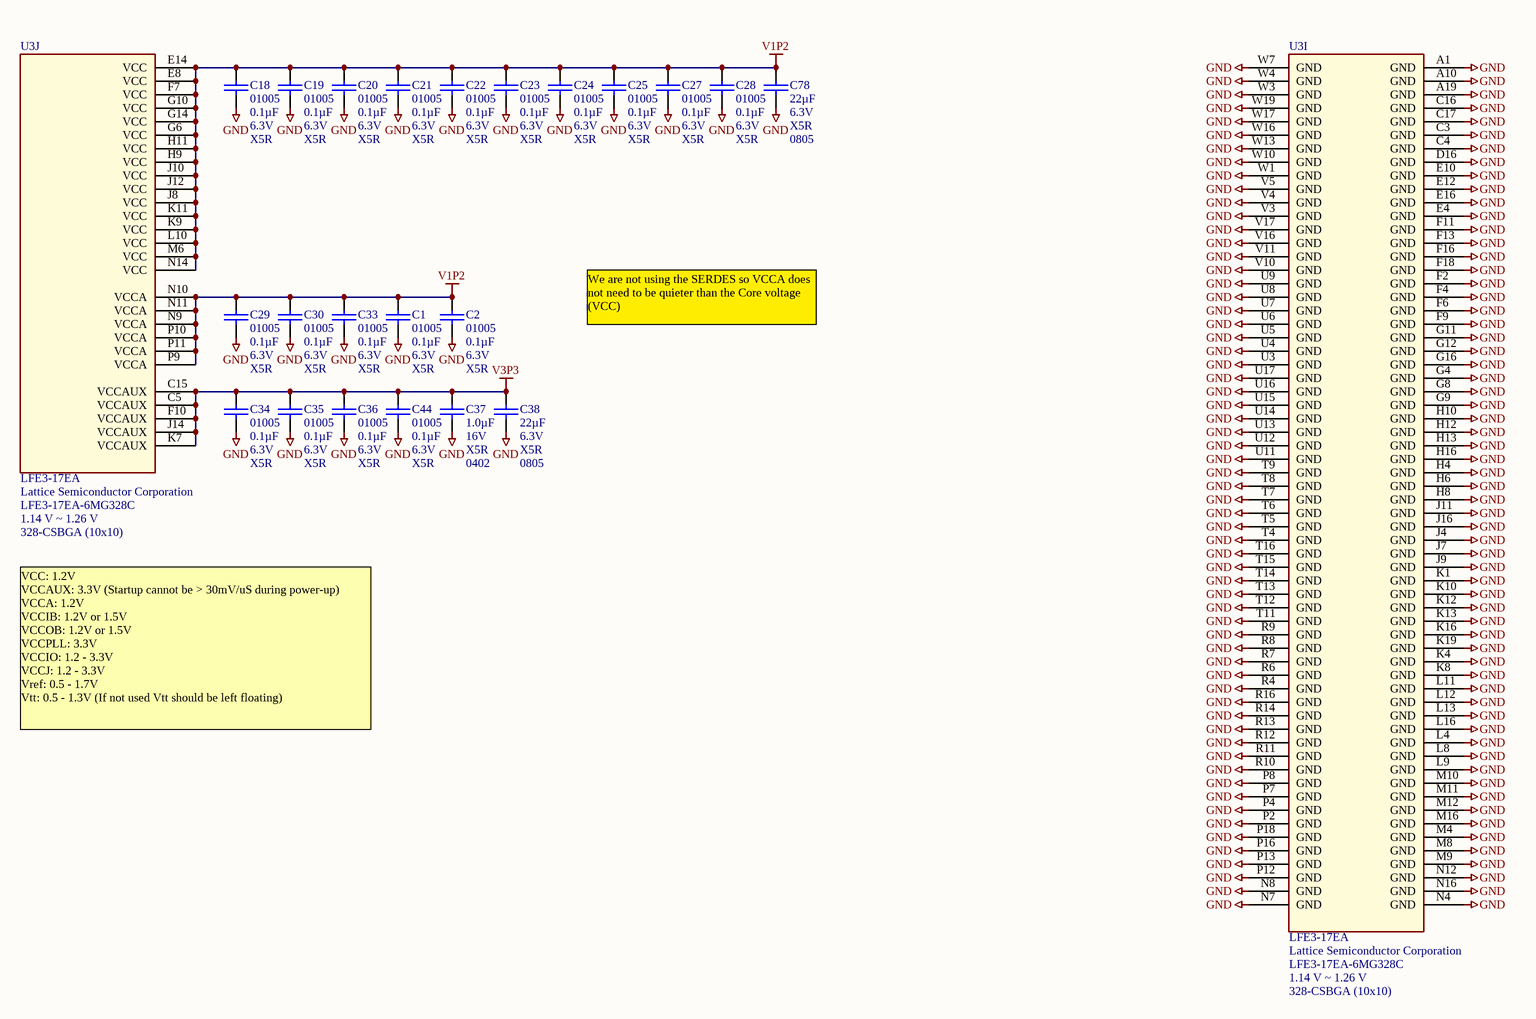
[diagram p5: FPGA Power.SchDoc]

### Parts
C1  Package / Case: 01005  Capacitance: 0.1µF  Voltage - Rated: 6.3V  Temperature Coefficient: X5R  [C_01005]  (hidden comment: 0.1uF)
C2  Package / Case: 01005  Capacitance: 0.1µF  Voltage - Rated: 6.3V  Temperature Coefficient: X5R  [C_01005]  (hidden comment: 0.1uF)
C18  Package / Case: 01005  Capacitance: 0.1µF  Voltage - Rated: 6.3V  Temperature Coefficient: X5R  [C_01005]  (hidden comment: 0.1uF)
C19  Package / Case: 01005  Capacitance: 0.1µF  Voltage - Rated: 6.3V  Temperature Coefficient: X5R  [C_01005]  (hidden comment: 0.1uF)
C20  Package / Case: 01005  Capacitance: 0.1µF  Voltage - Rated: 6.3V  Temperature Coefficient: X5R  [C_01005]  (hidden comment: 0.1uF)
C21  Package / Case: 01005  Capacitance: 0.1µF  Voltage - Rated: 6.3V  Temperature Coefficient: X5R  [C_01005]  (hidden comment: 0.1uF)
C22  Package / Case: 01005  Capacitance: 0.1µF  Voltage - Rated: 6.3V  Temperature Coefficient: X5R  [C_01005]  (hidden comment: 0.1uF)
C23  Package / Case: 01005  Capacitance: 0.1µF  Voltage - Rated: 6.3V  Temperature Coefficient: X5R  [C_01005]  (hidden comment: 0.1uF)
C24  Package / Case: 01005  Capacitance: 0.1µF  Voltage - Rated: 6.3V  Temperature Coefficient: X5R  [C_01005]  (hidden comment: 0.1uF)
C25  Package / Case: 01005  Capacitance: 0.1µF  Voltage - Rated: 6.3V  Temperature Coefficient: X5R  [C_01005]  (hidden comment: 0.1uF)
C27  Package / Case: 01005  Capacitance: 0.1µF  Voltage - Rated: 6.3V  Temperature Coefficient: X5R  [C_01005]  (hidden comment: 0.1uF)
C28  Package / Case: 01005  Capacitance: 0.1µF  Voltage - Rated: 6.3V  Temperature Coefficient: X5R  [C_01005]  (hidden comment: 0.1uF)
C29  Package / Case: 01005  Capacitance: 0.1µF  Voltage - Rated: 6.3V  Temperature Coefficient: X5R  [C_01005]  (hidden comment: 0.1uF)
C30  Package / Case: 01005  Capacitance: 0.1µF  Voltage - Rated: 6.3V  Temperature Coefficient: X5R  [C_01005]  (hidden comment: 0.1uF)
C33  Package / Case: 01005  Capacitance: 0.1µF  Voltage - Rated: 6.3V  Temperature Coefficient: X5R  [C_01005]  (hidden comment: 0.1uF)
C34  Package / Case: 01005  Capacitance: 0.1µF  Voltage - Rated: 6.3V  Temperature Coefficient: X5R  [C_01005]  (hidden comment: 0.1uF)
C35  Package / Case: 01005  Capacitance: 0.1µF  Voltage - Rated: 6.3V  Temperature Coefficient: X5R  [C_01005]  (hidden comment: 0.1uF)
C36  Package / Case: 01005  Capacitance: 0.1µF  Voltage - Rated: 6.3V  Temperature Coefficient: X5R  [C_01005]  (hidden comment: 0.1uF)
C37  Capacitance: 1.0µF  Voltage - Rated: 16V  Temperature Coefficient: X5R  Package / Case: 0402  [C_ERA-0402]  (hidden comment: 1.0uF)
C38  Capacitance: 22µF  Voltage - Rated: 6.3V  Temperature Coefficient: X5R  Package / Case: 0805  [C_ERA-0805]  (hidden comment: 22uF)
C44  Package / Case: 01005  Capacitance: 0.1µF  Voltage - Rated: 6.3V  Temperature Coefficient: X5R  [C_01005]  (hidden comment: 0.1uF)
C78  Capacitance: 22µF  Voltage - Rated: 6.3V  Temperature Coefficient: X5R  Package / Case: 0805  [C_ERA-0805]  (hidden comment: 22uF)
U3  LFE3-17EA  Manufacturer: Lattice Semiconductor Corporation  Manufacturer Part Number: LFE3-17EA-6MG328C  Voltage - Supply: 1.14 V ~ 1.26 V  Supplier Device Package: 328-CSBGA (10x10)  [BGA328C50P19X19_1000X1000X150]  (parts I,J of 10)

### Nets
GND: C1.1 C2.1 C18.1 C19.1 C20.1 C21.1 C22.1 C23.1 C24.1 C25.1 C27.1 C28.1 C29.1 C30.1 C33.1 C34.1 C35.1 C36.1 C37.1 C38.1 C44.1 C78.1 U3.A1(GND) U3.A10(GND) U3.A19(GND) U3.C3(GND) U3.C4(GND) U3.C16(GND) U3.C17(GND) U3.D16(GND) U3.E4(GND) U3.E10(GND) U3.E12(GND) U3.E16(GND) U3.F2(GND) U3.F4(GND) U3.F6(GND) U3.F9(GND) U3.F11(GND) U3.F13(GND) U3.F16(GND) U3.F18(GND) U3.G4(GND) U3.G8(GND) U3.G9(GND) U3.G11(GND) U3.G12(GND) U3.G16(GND) U3.H4(GND) U3.H6(GND) U3.H8(GND) U3.H10(GND) U3.H12(GND) U3.H13(GND) U3.H16(GND) U3.J4(GND) U3.J7(GND) U3.J9(GND) U3.J11(GND) U3.J16(GND) U3.K1(GND) U3.K4(GND) U3.K8(GND) U3.K10(GND) U3.K12(GND) U3.K13(GND) U3.K16(GND) U3.K19(GND) U3.L4(GND) U3.L8(GND) U3.L9(GND) U3.L11(GND) U3.L12(GND) U3.L13(GND) U3.L16(GND) U3.M4(GND) U3.M8(GND) U3.M9(GND) U3.M10(GND) U3.M11(GND) U3.M12(GND) U3.M16(GND) U3.N4(GND) U3.N7(GND) U3.N8(GND) U3.N12(GND) U3.N16(GND) U3.P2(GND) U3.P4(GND) U3.P7(GND) U3.P8(GND) U3.P12(GND) U3.P13(GND) U3.P16(GND) U3.P18(GND) U3.R4(GND) U3.R6(GND) U3.R7(GND) U3.R8(GND) U3.R9(GND) U3.R10(GND) U3.R11(GND) U3.R12(GND) U3.R13(GND) U3.R14(GND) U3.R16(GND) U3.T4(GND) U3.T5(GND) U3.T6(GND) U3.T7(GND) U3.T8(GND) U3.T9(GND) U3.T11(GND) U3.T12(GND) U3.T13(GND) U3.T14(GND) U3.T15(GND) U3.T16(GND) U3.U3(GND) U3.U4(GND) U3.U5(GND) U3.U6(GND) U3.U7(GND) U3.U8(GND) U3.U9(GND) U3.U11(GND) U3.U12(GND) U3.U13(GND) U3.U14(GND) U3.U15(GND) U3.U16(GND) U3.U17(GND) U3.V3(GND) U3.V4(GND) U3.V5(GND) U3.V10(GND) U3.V11(GND) U3.V16(GND) U3.V17(GND) U3.W1(GND) U3.W3(GND) U3.W4(GND) U3.W7(GND) U3.W10(GND) U3.W13(GND) U3.W16(GND) U3.W17(GND) U3.W19(GND)
V1P2: C1.2 C2.2 C18.2 C19.2 C20.2 C21.2 C22.2 C23.2 C24.2 C25.2 C27.2 C28.2 C29.2 C30.2 C33.2 C78.2 U3.E8(VCC) U3.E14(VCC) U3.F7(VCC) U3.G6(VCC) U3.G10(VCC) U3.G14(VCC) U3.H9(VCC) U3.H11(VCC) U3.J8(VCC) U3.J10(VCC) U3.J12(VCC) U3.K9(VCC) U3.K11(VCC) U3.L10(VCC) U3.M6(VCC) U3.N9(VCCA) U3.N10(VCCA) U3.N11(VCCA) U3.N14(VCC) U3.P9(VCCA) U3.P10(VCCA) U3.P11(VCCA)
V3P3: C34.2 C35.2 C36.2 C37.2 C38.2 C44.2 U3.C5(VCCAUX) U3.C15(VCCAUX) U3.F10(VCCAUX) U3.J14(VCCAUX) U3.K7(VCCAUX)

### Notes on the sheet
- We are not using the SERDES so VCCA does not need to be quieter than the Core voltage (VCC)
- VCC: 1.2V
  VCCAUX: 3.3V (Startup cannot be > 30mV/uS during power-up)
  VCCA: 1.2V
  VCCIB: 1.2V or 1.5V
  VCCOB: 1.2V or 1.5V
  VCCPLL: 3.3V
  VCCIO: 1.2 - 3.3V
  VCCJ: 1.2 - 3.3V
  Vref: 0.5 - 1.7V
  Vtt: 0.5 - 1.3V (If not used Vtt should be left floating)

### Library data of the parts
C1 C2 C18-C25 C27-C30 C33-C36 C44 = C_01005_0.1uF: as C3 on sheet FPGA Banks
C37 = C_0402_1.0UF_16V: as C16 on sheet FPGA Config
C38 C78 = C_0805_22UF_6.3V: CAP CER 22UF 6.3V X7R 10% 0805; Manufacturer: AVX Corporation; Manufacturer Part Number: 08056D226MAT2A; Tolerance: ±20%
U3 = U_LFE3-17EA-MG328: as U3 on sheet FPGA Banks

## Sheet FPGA SERDES.SchDoc: FPGA SERDES
size B; Date: 12/18/2013; DrawnBy: David McCoy; Engineer: David McCoy (Cospan Design); DocumentNumber: 10; Revision: C; SheetNumber: 10; SheetTotal: 13
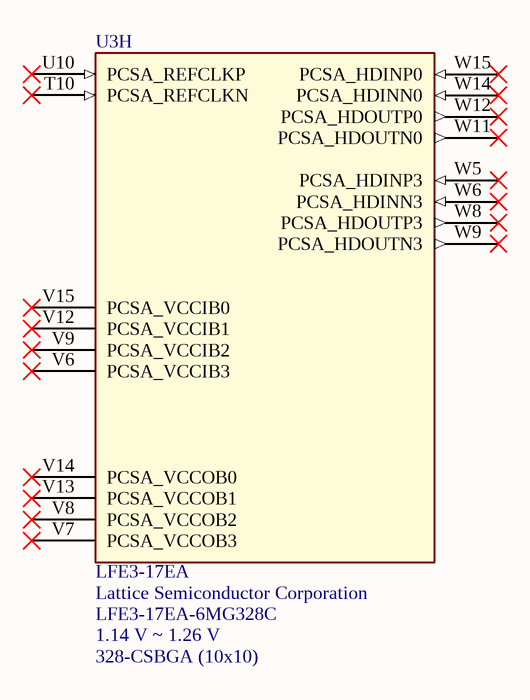
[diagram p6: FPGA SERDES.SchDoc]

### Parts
U3  LFE3-17EA  Manufacturer: Lattice Semiconductor Corporation  Manufacturer Part Number: LFE3-17EA-6MG328C  Voltage - Supply: 1.14 V ~ 1.26 V  Supplier Device Package: 328-CSBGA (10x10)  [BGA328C50P19X19_1000X1000X150]  (part H of 10)

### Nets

Not connected (* = marked no-connect by the designer): U3 T10(PCSA_REFCLKN)* U10(PCSA_REFCLKP)* V6(PCSA_VCCIB3)* V7(PCSA_VCCOB3)* V8(PCSA_VCCOB2)* V9(PCSA_VCCIB2)* V12(PCSA_VCCIB1)* V13(PCSA_VCCOB1)* V14(PCSA_VCCOB0)* V15(PCSA_VCCIB0)* W5(PCSA_HDINP3)* W6(PCSA_HDINN3)* W8(PCSA_HDOUTP3)* W9(PCSA_HDOUTN3)* W11(PCSA_HDOUTN0)* W12(PCSA_HDOUTP0)* W14(PCSA_HDINN0)* W15(PCSA_HDINP0)*

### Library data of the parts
U3 = U_LFE3-17EA-MG328: as U3 on sheet FPGA Banks

## Sheet Power.SchDoc: Power
size B; Date: 12/18/2013; DrawnBy: David McCoy; Engineer: David McCoy (Cospan Design); DocumentNumber: 13; Revision: C; SheetNumber: 13; SheetTotal: 13
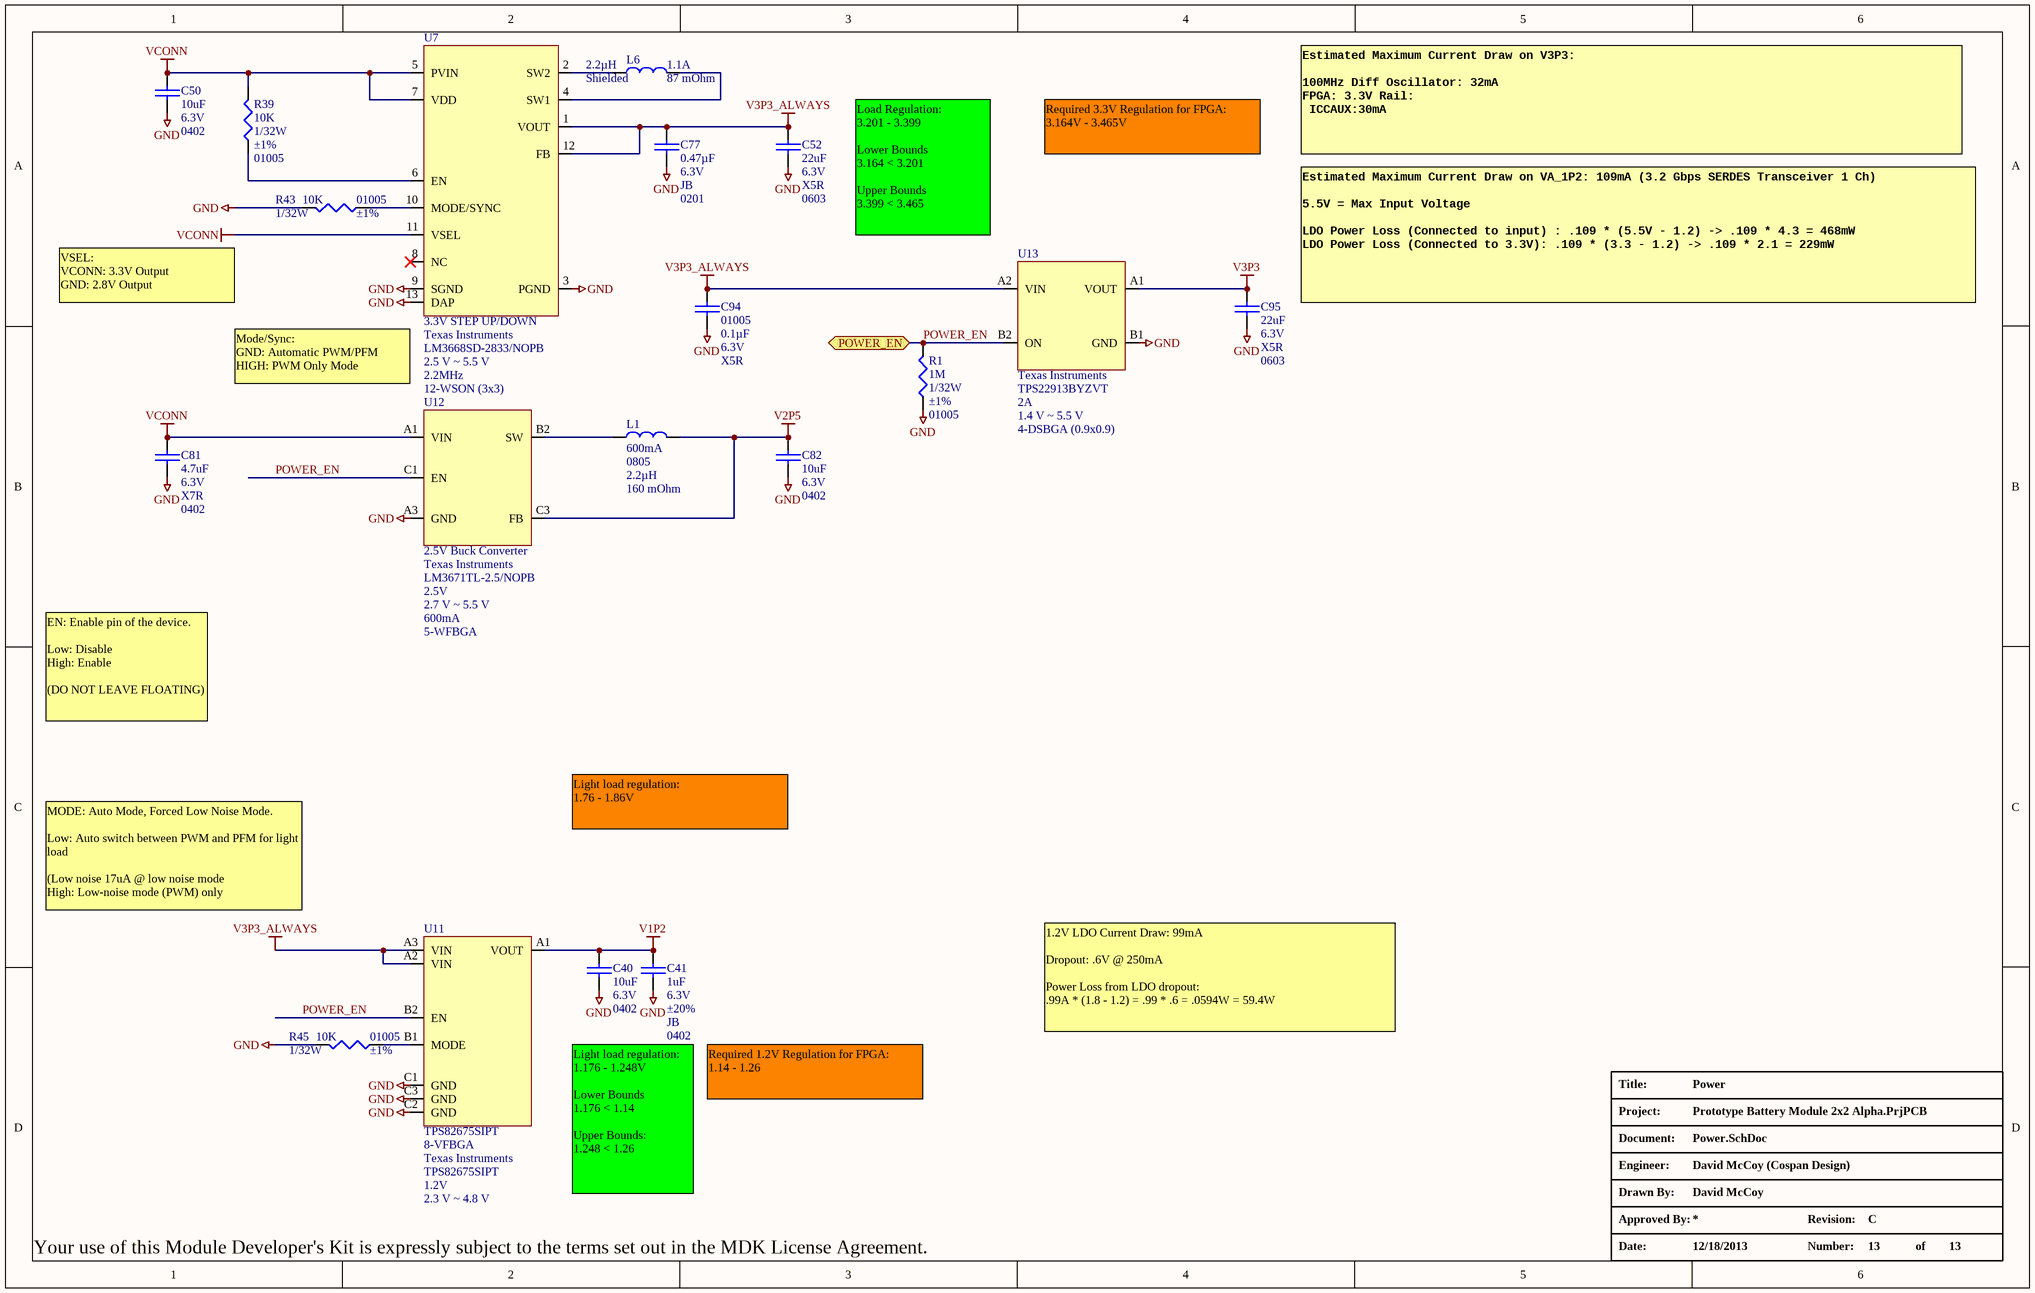
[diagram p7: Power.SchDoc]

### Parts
C40  Voltage - Rated: 6.3V  Package / Case: 0402  [C_0402]  (hidden comment: 10uF)
C41  Voltage - Rated: 6.3V  Tolerance: ±20%  Temperature Coefficient: JB  Package / Case: 0402  [C_0402]  (hidden comment: 1uF)
C50  Voltage - Rated: 6.3V  Package / Case: 0402  [C_0402]  (hidden comment: 10uF)
C52  Voltage - Rated: 6.3V  Temperature Coefficient: X5R  Package / Case: 0603  [C_ERA-0603]  (hidden comment: 22uF)
C77  Voltage - Rated: 6.3V  Temperature Coefficient: JB  Package / Case: 0201  [CAPC0201]  (hidden comment: 0.47µF)
C81  Voltage - Rated: 6.3V  Temperature Coefficient: X7R  Package / Case: 0402  [C_0402]  (hidden comment: 4.7uF)
C82  Voltage - Rated: 6.3V  Package / Case: 0402  [C_0402]  (hidden comment: 10uF)
C94  Package / Case: 01005  Capacitance: 0.1µF  Voltage - Rated: 6.3V  Temperature Coefficient: X5R  [C_01005]  (hidden comment: 0.1uF)
C95  Voltage - Rated: 6.3V  Temperature Coefficient: X5R  Package / Case: 0603  [C_ERA-0603]  (hidden comment: 22uF)
L1  Current: 600mA  Package / Case: 0805  Inductance: 2.2µH  DC Resistance (DCR): 160 mOhm  [C_ERA-0805]  (hidden comment: 2.2uH)
L6  Inductance: 2.2µH  Current - Saturation: 1.1A  Shielding: Shielded  DC Resistance (DCR): 87 mOhm  [L_SMD_2.2uH]  (hidden comment: 2.2uH Wirewound)
R1  Resistance In Ohms: 1M  Power (Watts): 1/32W  Tolerance: ±1%  Case: 01005  [R_01005]  (hidden comment: 1M Ohms)
R39  Power (Watts): 1/32W  Tolerance: ±1%  Case: 01005  [R_01005]  (hidden comment: 10K)
R43  Power (Watts): 1/32W  Tolerance: ±1%  Case: 01005  [R_01005]  (hidden comment: 10K)
R45  Power (Watts): 1/32W  Tolerance: ±1%  Case: 01005  [R_01005]  (hidden comment: 10K)
U7  3.3V STEP UP/DOWN  Manufacturer: Texas Instruments  Manufacturer Part Number: LM3668SD-2833/NOPB  Voltage - Input: 2.5 V ~ 5.5 V  Frequency - Switching: 2.2MHz  Supplier Device Package: 12-WSON (3x3)  [QFN40P300X300X80_HS-13L]
U11  TPS82675SIPT  Package / Case: 8-VFBGA  Manufacturer: Texas Instruments  Voltage - Output: 1.2V  Voltage - Input: 2.3 V ~ 4.8 V  [MICRP SIP]
U12  2.5V Buck Converter  Manufacturer: Texas Instruments  Manufacturer Part Number: LM3671TL-2.5/NOPB  Voltage - Output: 2.5V  Voltage - Input: 2.7 V ~ 5.5 V  Current - Output: 600mA  Package / Case: 5-WFBGA  [BGA4C50P2X2_105X138X60]
U13  Manufacturer: Texas Instruments  Manufacturer Part Number: TPS22913BYZVT  Current Limit: 2A  Voltage - Input: 1.4 V ~ 5.5 V  Supplier Device Package: 4-DSBGA (0.9x0.9)  [DSBGA4 _.5MM]  (hidden comment: Power Switch)

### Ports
POWER_EN

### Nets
GND: C40.1 C41.1 C50.1 C52.1 C77.1 C81.1 C82.1 C94.1 C95.1 R1.2 R43.1 R45.1 U7.3(PGND) U7.9(SGND) U7.13(DAP) U11.C1(GND) U11.C2(GND) U11.C3(GND) U12.A3(GND) U13.B1(GND)
V1P2: C40.2 C41.2 U11.A1(VOUT)
V2P5: C82.2 L1.2 U12.C3(FB)
V3P3: C95.2 U13.A1(VOUT)
V3P3_ALWAYS: C52.2 C77.2 C94.2 U7.1(VOUT) U7.12(FB) U11.A2(VIN) U11.A3(VIN) U13.A2(VIN)
VCONN: C50.2 C81.2 R39.1 U7.5(PVIN) U7.7(VDD) U7.11(VSEL) U12.A1(VIN)
POWER_EN: R1.1 U11.B2(EN) U12.C1(EN) U13.B2(ON) ; port POWER_EN
NetL1_1: L1.1 U12.B2(SW)
NetL6_1: L6.1 U7.2(SW2)
NetL6_2: L6.2 U7.4(SW1)
NetR39_2: R39.2 U7.6(EN)
NetR43_2: R43.2 U7.10(MODE/SYNC)
NetR45_2: R45.2 U11.B1(MODE)

Not connected (* = marked no-connect by the designer): U7 8(NC)*

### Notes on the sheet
- Required 3.3V Regulation for FPGA:
  3.164V - 3.465V
- Estimated Maximum Current Draw on V3P3:
  100MHz Diff Oscillator: 32mA
  FPGA: 3.3V Rail:
  ICCAUX:30mA
- Load Regulation:
  3.201 - 3.399
  Lower Bounds
  3.164 < 3.201
  Upper Bounds
  3.399 < 3.465
- VSEL:
  VCONN: 3.3V Output
  GND: 2.8V Output
- Estimated Maximum Current Draw on VA_1P2: 109mA (3.2 Gbps SERDES Transceiver 1 Ch)
  5.5V = Max Input Voltage
  LDO Power Loss (Connected to input) : .109 * (5.5V - 1.2) -> .109 * 4.3 = 468mW
  LDO Power Loss (Connected to 3.3V): .109 * (3.3 - 1.2) -> .109 * 2.1 = 229mW
- (near U7) Mode/Sync:
  GND: Automatic PWM/PFM
  HIGH: PWM Only Mode
- EN: Enable pin of the device.
  Low: Disable
  High: Enable
  (DO NOT LEAVE FLOATING)
- Light load regulation:
  1.76 - 1.86V
- MODE: Auto Mode, Forced Low Noise Mode.
  Low: Auto switch between PWM and PFM for light load
  (Low noise 17uA @ low noise mode
  High: Low-noise mode (PWM) only
- 1.2V LDO Current Draw: 99mA
  Dropout: .6V @ 250mA
  Power Loss from LDO dropout:
  .99A * (1.8 - 1.2) = .99 * .6 = .0594W = 59.4W
- Required 1.2V Regulation for FPGA:
  1.14 - 1.26
- (near U11) Light load regulation:
  1.176 - 1.248V
  Lower Bounds
  1.176 < 1.14
  Upper Bounds:
  1.248 < 1.26

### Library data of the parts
C40 C50 C82 = C_0402_10uF: as C59 on sheet FPGA Banks
C41 = C_0402_1uF: CAP CER 1UF 6.3V 20% JB 0402; Manufacturer: TDK Corporation; Manufacturer Part Number: C1005JB0J105M050BB
C52 C95 = C_0603_22uF: CAP CER 22UF 6.3V 20% X5R 0603; Manufacturer: TDK Corporation; Manufacturer Part Number: C1608X5R0J226M080AC
C77 = C_0201_0.47µF: as C57 on sheet FPGA Banks
C81 = C_0402_4.7uF: CAP CER 4.7UF 6.3V 10% X7R 0603; Manufacturer: Samsung Electro-Mechanics America, Inc; Manufacturer Part Number: CL10B475KQ8NQNC
C94 = C_01005_0.1uF: as C3 on sheet FPGA Banks
L1 = L_0805_2.2uH_160mOhm: INDUCTOR MULTILAYER 2.2UH 0805; Manufacturer: TDK Corporation; Manufacturer Part Number: MLZ2012M2R2H; Material - Core: Ferrite; Tolerance: ±20%; Current - Saturation: 400mA; Shielding: Shielded; Frequency - Self Resonant: 100MHz; Frequency - Test: 2MHz
L6 = L_SMD_2.2uH: COIL CHOKE 2.2UH SHIELDED SMD; Manufacturer: Panasonic Electronic Components; Manufacturer Part Number: ELL-VFG2R2NC; Tolerance: ±30%; Current Rating: 1.4A; Frequency - Test: 100kHz
R1 = R_01005_1M: RES 1M OHM 1/32W 1% 01005 SMD; Manufacturer: Yageo; Manufacturer Part Number: RC0100FR-071ML; Temperature Coefficient: ±250ppm/°C
R39 R43 R45 = R_01005_10K: as R22 on sheet FPGA Config
U7 = U_LM3668SD-2833/NOPB: IC REG BUCK BST SYNC ADJ 12-LLP; Output Type: Adjustable; Number of Outputs: 1; Voltage - Output: 2.8 V ~ 3.3 V; PWM Type: Voltage Mode; Current - Output: 1A; Synchronous Rectifier: Yes
U11 = U_TPS82675SIPT: IC REG BUCK SYNC 1.2V 0.6A 8USIP; Output Type: Fixed; Number of Outputs: 1; PWM Type: Voltage Mode; Frequency - Switching: 5.45MHz; Current - Output: 600mA; Synchronous Rectifier: Yes
U12 = U_LM3671TL-2.5/NOPB: IC REG BUCK SYNC 2.5V 0.6A 5USMD; Output Type: Fixed; Number of Outputs: 1; PWM Type: Voltage Mode; Frequency - Switching: 2MHz; Synchronous Rectifier: Yes
U13 = U_TPS22913BYZVT: IC LOAD SWITCH 5V 4DSBGA; Number of Outputs: 1; Rds (On): 80 mOhm; Internal Switch(s): Yes

## Sheet EPM.SchDoc: EPM
size B; Date: 12/18/2013; DrawnBy: David McCoy; Engineer: David McCoy (Cospan Design); DocumentNumber: 9; Revision: C; SheetNumber: 9; SheetTotal: 13
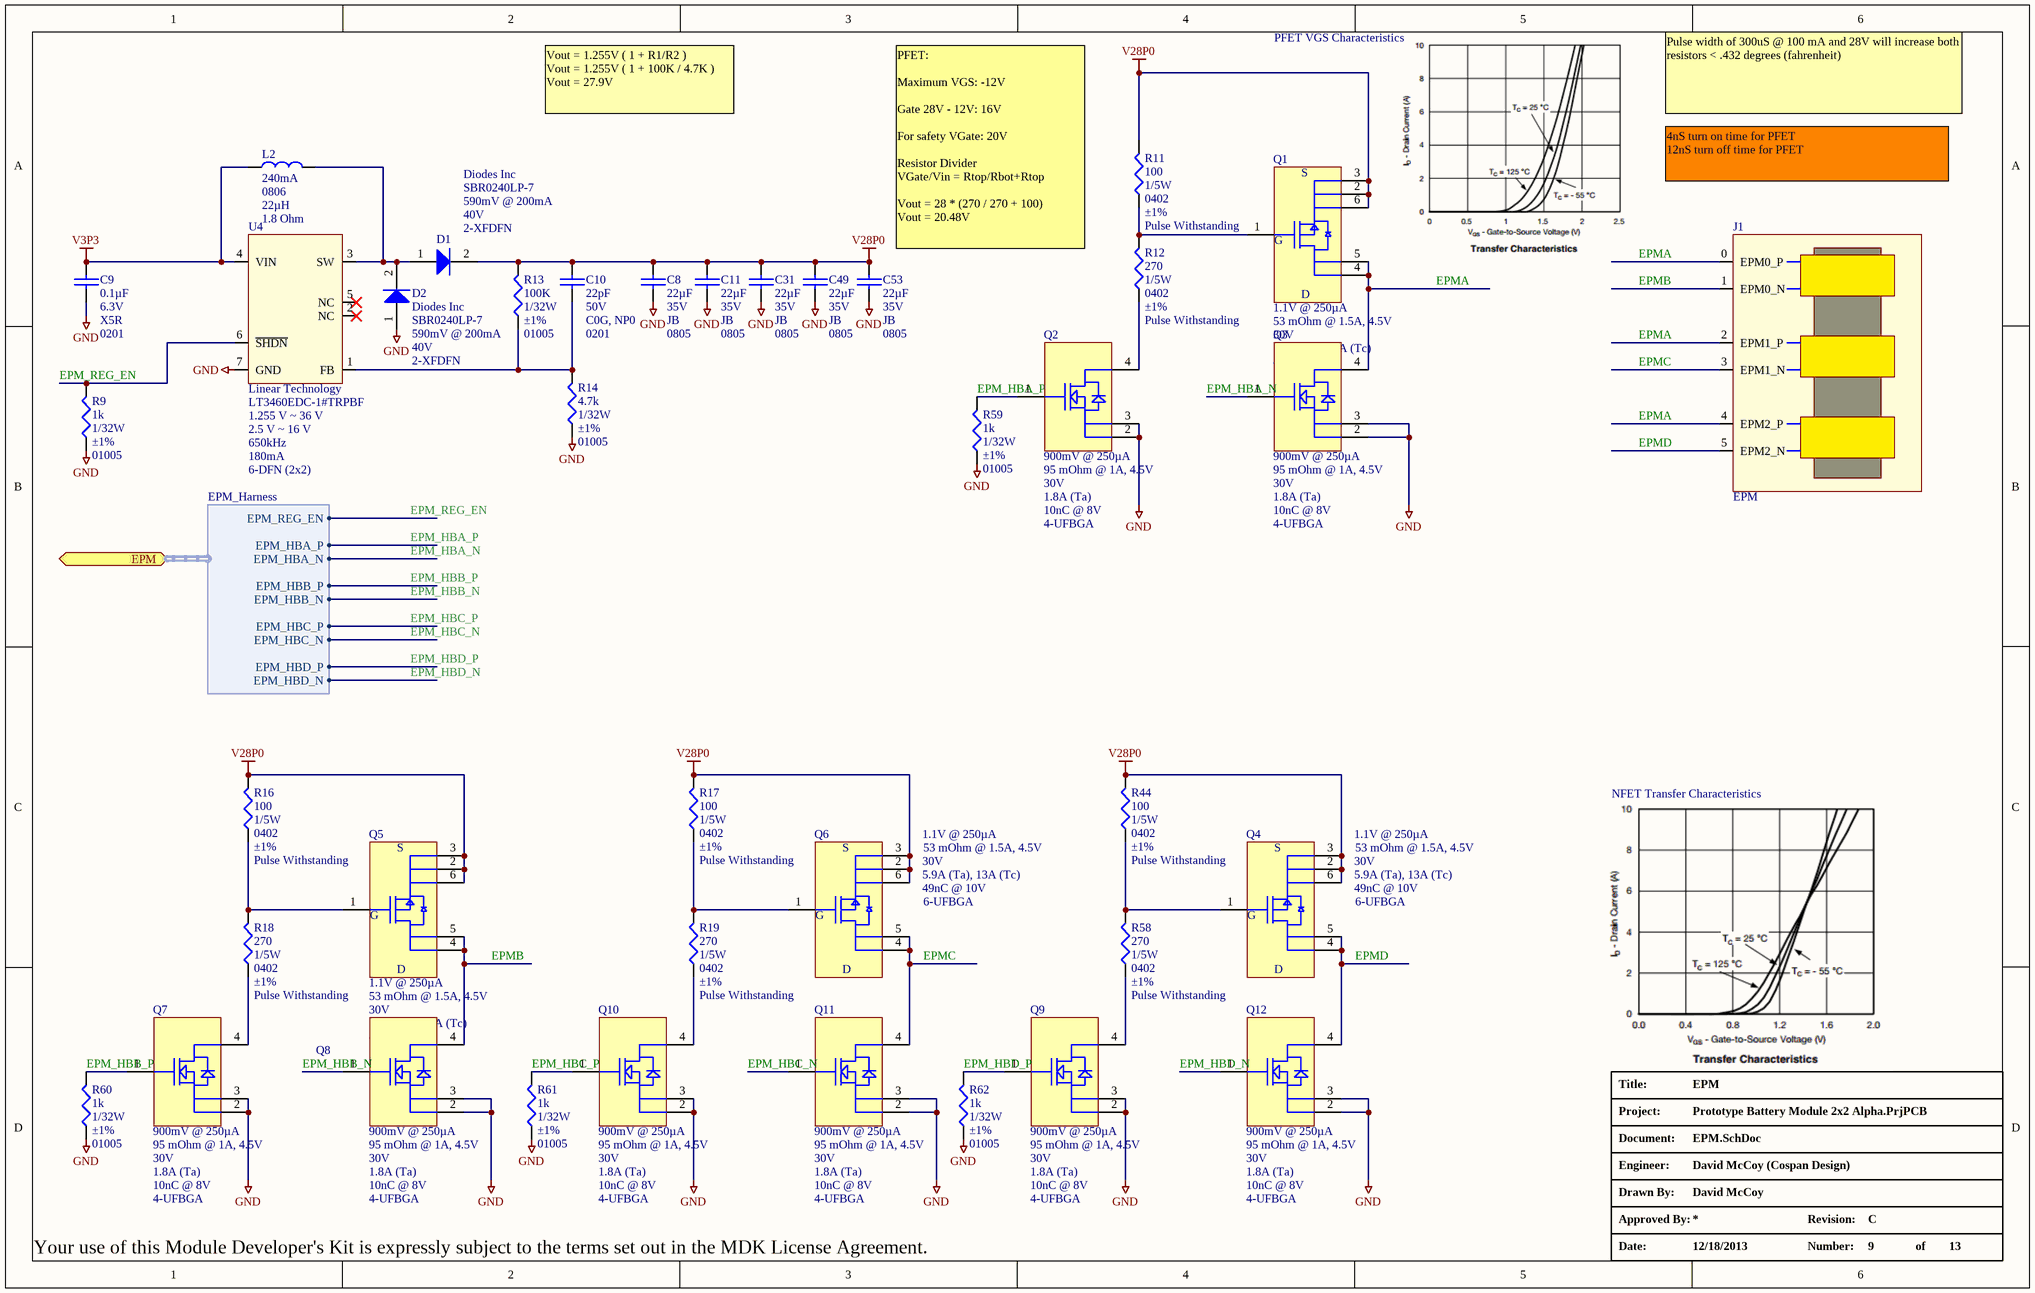
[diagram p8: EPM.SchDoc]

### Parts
C8  Voltage - Rated: 35V  Temperature Coefficient: JB  Package / Case: 0805  [C_ERA-0805]  (hidden comment: 22µF)
C9  Capacitance: 0.1µF  Voltage - Rated: 6.3V  Temperature Coefficient: X5R  Package / Case: 0201  [CAPC0201]  (hidden comment: 0.1UF)
C10  Capacitance: 22pF  Voltage - Rated: 50V  Temperature Coefficient: C0G, NP0  Package / Case: 0201  [CAPC0201]  (hidden comment: C_0201_22pF)
C11  Voltage - Rated: 35V  Temperature Coefficient: JB  Package / Case: 0805  [C_ERA-0805]  (hidden comment: 22µF)
C31  Voltage - Rated: 35V  Temperature Coefficient: JB  Package / Case: 0805  [C_ERA-0805]  (hidden comment: 22µF)
C49  Voltage - Rated: 35V  Temperature Coefficient: JB  Package / Case: 0805  [C_ERA-0805]  (hidden comment: 22µF)
C53  Voltage - Rated: 35V  Temperature Coefficient: JB  Package / Case: 0805  [C_ERA-0805]  (hidden comment: 22µF)
D1  Manufacturer: Diodes Inc  Voltage - Forward (Vf) (Max) @ If: 590mV @ 200mA  Voltage - DC Reverse (Vr) (Max): 40V  [2-XFDFN]  (hidden comment: SBR0240LP-7)
D2  Manufacturer: Diodes Inc  Voltage - Forward (Vf) (Max) @ If: 590mV @ 200mA  Voltage - DC Reverse (Vr) (Max): 40V  [2-XFDFN]  (hidden comment: SBR0240LP-7)
J1  EPM  [EPM_3X_CONNECTION]  (no BOM)
L2  Current: 240mA  Package / Case: 0806  Inductance: 22µH  DC Resistance (DCR): 1.8 Ohm  [L_0806]  (hidden comment: CBC2016T220K)
Q1  Vgs(th) (Max) @ Id: 1.1V @ 250µA  Rds On (Max) @ Id, Vgs: 53 mOhm @ 1.5A, 4.5V  Drain to Source Voltage (Vdss): 30V  Current - Continuous Drain (Id) @ 25° C: 5.9A (Ta), 13A (Tc)  Gate Charge (Qg) @ Vgs: 49nC @ 10V  Supplier Device Package: 6-UFBGA  [BGA6C50P3X2_145X96X59]  (hidden comment: SI8497DB-T2-E1)
Q2  Vgs(th) (Max) @ Id: 900mV @ 250µA  Rds On (Max) @ Id, Vgs: 95 mOhm @ 1A, 4.5V  Drain to Source Voltage (Vdss): 30V  Current - Continuous Drain (Id) @ 25° C: 1.8A (Ta)  Gate Charge (Qg) @ Vgs: 10nC @ 8V  Supplier Device Package: 4-UFBGA  [BGA4C40P2X2_80X80X40]  (hidden comment: SI8808DB-T2-E1)
Q3  Vgs(th) (Max) @ Id: 900mV @ 250µA  Rds On (Max) @ Id, Vgs: 95 mOhm @ 1A, 4.5V  Drain to Source Voltage (Vdss): 30V  Current - Continuous Drain (Id) @ 25° C: 1.8A (Ta)  Gate Charge (Qg) @ Vgs: 10nC @ 8V  Supplier Device Package: 4-UFBGA  [BGA4C40P2X2_80X80X40]  (hidden comment: SI8808DB-T2-E1)
Q4  Vgs(th) (Max) @ Id: 1.1V @ 250µA  Rds On (Max) @ Id, Vgs: 53 mOhm @ 1.5A, 4.5V  Drain to Source Voltage (Vdss): 30V  Current - Continuous Drain (Id) @ 25° C: 5.9A (Ta), 13A (Tc)  Gate Charge (Qg) @ Vgs: 49nC @ 10V  Supplier Device Package: 6-UFBGA  [BGA6C50P3X2_145X96X59]  (hidden comment: SI8497DB-T2-E1)
Q5  Vgs(th) (Max) @ Id: 1.1V @ 250µA  Rds On (Max) @ Id, Vgs: 53 mOhm @ 1.5A, 4.5V  Drain to Source Voltage (Vdss): 30V  Current - Continuous Drain (Id) @ 25° C: 5.9A (Ta), 13A (Tc)  Gate Charge (Qg) @ Vgs: 49nC @ 10V  Supplier Device Package: 6-UFBGA  [BGA6C50P3X2_145X96X59]  (hidden comment: SI8497DB-T2-E1)
Q6  Vgs(th) (Max) @ Id: 1.1V @ 250µA  Rds On (Max) @ Id, Vgs: 53 mOhm @ 1.5A, 4.5V  Drain to Source Voltage (Vdss): 30V  Current - Continuous Drain (Id) @ 25° C: 5.9A (Ta), 13A (Tc)  Gate Charge (Qg) @ Vgs: 49nC @ 10V  Supplier Device Package: 6-UFBGA  [BGA6C50P3X2_145X96X59]  (hidden comment: SI8497DB-T2-E1)
Q7  Vgs(th) (Max) @ Id: 900mV @ 250µA  Rds On (Max) @ Id, Vgs: 95 mOhm @ 1A, 4.5V  Drain to Source Voltage (Vdss): 30V  Current - Continuous Drain (Id) @ 25° C: 1.8A (Ta)  Gate Charge (Qg) @ Vgs: 10nC @ 8V  Supplier Device Package: 4-UFBGA  [BGA4C40P2X2_80X80X40]  (hidden comment: SI8808DB-T2-E1)
Q8  Vgs(th) (Max) @ Id: 900mV @ 250µA  Rds On (Max) @ Id, Vgs: 95 mOhm @ 1A, 4.5V  Drain to Source Voltage (Vdss): 30V  Current - Continuous Drain (Id) @ 25° C: 1.8A (Ta)  Gate Charge (Qg) @ Vgs: 10nC @ 8V  Supplier Device Package: 4-UFBGA  [BGA4C40P2X2_80X80X40]  (hidden comment: SI8808DB-T2-E1)
Q9  Vgs(th) (Max) @ Id: 900mV @ 250µA  Rds On (Max) @ Id, Vgs: 95 mOhm @ 1A, 4.5V  Drain to Source Voltage (Vdss): 30V  Current - Continuous Drain (Id) @ 25° C: 1.8A (Ta)  Gate Charge (Qg) @ Vgs: 10nC @ 8V  Supplier Device Package: 4-UFBGA  [BGA4C40P2X2_80X80X40]  (hidden comment: SI8808DB-T2-E1)
Q10  Vgs(th) (Max) @ Id: 900mV @ 250µA  Rds On (Max) @ Id, Vgs: 95 mOhm @ 1A, 4.5V  Drain to Source Voltage (Vdss): 30V  Current - Continuous Drain (Id) @ 25° C: 1.8A (Ta)  Gate Charge (Qg) @ Vgs: 10nC @ 8V  Supplier Device Package: 4-UFBGA  [BGA4C40P2X2_80X80X40]  (hidden comment: SI8808DB-T2-E1)
Q11  Vgs(th) (Max) @ Id: 900mV @ 250µA  Rds On (Max) @ Id, Vgs: 95 mOhm @ 1A, 4.5V  Drain to Source Voltage (Vdss): 30V  Current - Continuous Drain (Id) @ 25° C: 1.8A (Ta)  Gate Charge (Qg) @ Vgs: 10nC @ 8V  Supplier Device Package: 4-UFBGA  [BGA4C40P2X2_80X80X40]  (hidden comment: SI8808DB-T2-E1)
Q12  Vgs(th) (Max) @ Id: 900mV @ 250µA  Rds On (Max) @ Id, Vgs: 95 mOhm @ 1A, 4.5V  Drain to Source Voltage (Vdss): 30V  Current - Continuous Drain (Id) @ 25° C: 1.8A (Ta)  Gate Charge (Qg) @ Vgs: 10nC @ 8V  Supplier Device Package: 4-UFBGA  [BGA4C40P2X2_80X80X40]  (hidden comment: SI8808DB-T2-E1)
R9  Power (Watts): 1/32W  Tolerance: ±1%  Case: 01005  [R_01005]  (hidden comment: 1k)
R11  Power (Watts): 1/5W  Case: 0402  Tolerance: ±1%  [R_0402]  (hidden comment: 100)
R12  Power (Watts): 1/5W  Case: 0402  Tolerance: ±1%  [R_0402]  (hidden comment: 270)
R13  Resistance In Ohms: 100K  Power (Watts): 1/32W  Tolerance: ±1%  Case: 01005  [R_01005]  (hidden comment: 10K)
R14  Power (Watts): 1/32W  Tolerance: ±1%  Case: 01005  [R_01005]  (hidden comment: 4.7k)
R16  Power (Watts): 1/5W  Case: 0402  Tolerance: ±1%  [R_0402]  (hidden comment: 100)
R17  Power (Watts): 1/5W  Case: 0402  Tolerance: ±1%  [R_0402]  (hidden comment: 100)
R18  Power (Watts): 1/5W  Case: 0402  Tolerance: ±1%  [R_0402]  (hidden comment: 270)
R19  Power (Watts): 1/5W  Case: 0402  Tolerance: ±1%  [R_0402]  (hidden comment: 270)
R44  Power (Watts): 1/5W  Case: 0402  Tolerance: ±1%  [R_0402]  (hidden comment: 100)
R58  Power (Watts): 1/5W  Case: 0402  Tolerance: ±1%  [R_0402]  (hidden comment: 270)
R59  Power (Watts): 1/32W  Tolerance: ±1%  Case: 01005  [R_01005]  (hidden comment: 1k)
R60  Power (Watts): 1/32W  Tolerance: ±1%  Case: 01005  [R_01005]  (hidden comment: 1k)
R61  Power (Watts): 1/32W  Tolerance: ±1%  Case: 01005  [R_01005]  (hidden comment: 1k)
R62  Power (Watts): 1/32W  Tolerance: ±1%  Case: 01005  [R_01005]  (hidden comment: 1k)
U4  Manufacturer: Linear Technology  Manufacturer Part Number: LT3460EDC-1#TRPBF  Voltage - Output: 1.255 V ~ 36 V  Voltage - Input: 2.5 V ~ 16 V  Frequency - Switching: 650kHz  Current - Output: 180mA  Supplier Device Package: 6-DFN (2x2)  [DFN6]  (hidden comment: U_LT3460EDC-1)

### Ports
EPM (harness EPM_Harness)

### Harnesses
EPM_Harness: EPM_REG_EN, EPM_HBA_P, EPM_HBA_N, EPM_HBB_P, EPM_HBB_N, EPM_HBC_P, EPM_HBC_N, EPM_HBD_P, EPM_HBD_N

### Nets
GND: C8.1 C9.1 C11.1 C31.1 C49.1 C53.1 D2.1(A) Q2.2(S2) Q2.3(S) Q3.2(S2) Q3.3(S) Q7.2(S2) Q7.3(S) Q8.2(S2) Q8.3(S) Q9.2(S2) Q9.3(S) Q10.2(S2) Q10.3(S) Q11.2(S2) Q11.3(S) Q12.2(S2) Q12.3(S) R9.2 R14.2 R59.2 R60.2 R61.2 R62.2 U4.7(GND)
V3P3: C9.2 L2.1 U4.4(VIN)
V28P0: C8.2 C10.2 C11.2 C31.2 C49.2 C53.2 D1.2(K) Q1.2(S2) Q1.3(S) Q1.6(S3) Q4.2(S2) Q4.3(S) Q4.6(S3) Q5.2(S2) Q5.3(S) Q5.6(S3) Q6.2(S2) Q6.3(S) Q6.6(S3) R11.1 R13.1 R16.1 R17.1 R44.1
EPM_HBA_N: Q3.1(G) ; port EPM.EPM_HBA_N
EPM_HBA_P: Q2.1(G) R59.1 ; port EPM.EPM_HBA_P
EPM_HBB_N: Q8.1(G) ; port EPM.EPM_HBB_N
EPM_HBB_P: Q7.1(G) R60.1 ; port EPM.EPM_HBB_P
EPM_HBC_N: Q11.1(G) ; port EPM.EPM_HBC_N
EPM_HBC_P: Q10.1(G) R61.1 ; port EPM.EPM_HBC_P
EPM_HBD_N: Q12.1(G) ; port EPM.EPM_HBD_N
EPM_HBD_P: Q9.1(G) R62.1 ; port EPM.EPM_HBD_P
EPM_REG_EN: R9.1 U4.6(~{SHDN}) ; port EPM.EPM_REG_EN
EPMA: J1.0(EPM0_P) J1.2(EPM1_P) J1.4(EPM2_P) Q1.4(D1) Q1.5(D2) Q3.4(D)
EPMB: J1.1(EPM0_N) Q5.4(D1) Q5.5(D2) Q8.4(D)
EPMC: J1.3(EPM1_N) Q6.4(D1) Q6.5(D2) Q11.4(D)
EPMD: J1.5(EPM2_N) Q4.4(D1) Q4.5(D2) Q12.4(D)
NetC10_1: C10.1 R13.2 R14.1 U4.1(FB)
NetD1_1: D1.1(A) D2.2(K) L2.2 U4.3(SW)
NetQ1_1: Q1.1(G) R11.2 R12.1
NetQ2_4: Q2.4(D) R12.2
NetQ4_1: Q4.1(G) R44.2 R58.1
NetQ5_1: Q5.1(G) R16.2 R18.1
NetQ6_1: Q6.1(G) R17.2 R19.1
NetQ7_4: Q7.4(D) R18.2
NetQ9_4: Q9.4(D) R58.2
NetQ10_4: Q10.4(D) R19.2

Not connected (* = marked no-connect by the designer): U4 2(NC)* 5(NC)*

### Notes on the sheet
- PFET VGS Characteristics
- Vout = 1.255V ( 1 + R1/R2 )
  Vout = 1.255V ( 1 + 100K / 4.7K )
  Vout = 27.9V
- Pulse width of 300uS @ 100 mA and 28V will increase both resistors < .432 degrees (fahrenheit)
- 4nS turn on time for PFET
  12nS turn off time for PFET
- PFET:
  Maximum VGS: -12V
  Gate 28V - 12V: 16V
  For safety VGate: 20V
  Resistor Divider
  VGate/Vin = Rtop/Rbot+Rtop
  Vout = 28 * (270 / 270 + 100)
  Vout = 20.48V
- NFET Transfer Characteristics

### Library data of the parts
C8 C11 C31 C49 C53 = C_0805_22µF_35V: CAP CER 22UF 35V 20% JB 0805; Manufacturer: TDK Corporation; Manufacturer Part Number: C2012JB1V226M125AC
C9 = C_0201_0.1UF: CAP CER 0.1UF 6.3V 10% X5R 0201; Manufacturer: TDK Corporation; Manufacturer Part Number: C0603X5R0J104M; Tolerance: ±20%
C10 = C_0201_22pF: CAP CER 22PF 50V 5% NP0 0201; Manufacturer: TDK Corporation; Manufacturer Part Number: C0603C0G1H220J030BA
D1 D2 = D_SBR0240LP-7: DIODE SUP BARRIER 40V 0.25A 2DFN; Diode Type: Super Barrier; Current - Average Rectified (Io): 250mA; Speed: Fast Recovery =< 500ns, > 200mA (Io); Current - Reverse Leakage @ Vr: 10µA @ 40V; Thermal Resistance: 270°C/W Ja
J1 = J_EPM_3_PAD
L2 = L_0806_22uH: INDUCTOR 22UH 10% 0806 SMD; Manufacturer: Taiyo Yuden; Type: Wirewound; Current - Saturation: 250mA; Shielding: Unshielded; Frequency - Self Resonant: 16MHz; Frequency - Test: 2.52MHz
Q1 Q4-Q6 = Q_PFET_BGA_30V: MOSFET P-CH D-S 30V MICROFOOT; Manufacturer: Vishay Siliconix; FET Type: MOSFET P-Channel, Metal Oxide; FET Feature: Logic Level Gate, 2.5V Drive; Input Capacitance (Ciss) @ Vds: 1320pF @ 15V; Power - Max: 13W
Q2 Q3 Q7-Q12 = Q_NFET_BGA_30V: MOSFET N-CH D-S 30V MICROFOOT; Manufacturer: Vishay Siliconix; FET Type: MOSFET N-Channel, Metal Oxide; FET Feature: Logic Level Gate, 1.5V Drive; Input Capacitance (Ciss) @ Vds: 330pF @ 15V
R9 R59-R62 = R_01005_1k: as R20 on sheet FPGA Config
R11 R16 R17 R44 = R_0402_100_5%_PW: RES 100 OHM 1/5W 5% 0402 SMD; Manufacturer: Rohm Semiconductor; Manufacturer Part Number: ESR01MZPJ101; Temperature Coefficient: ±200ppm/°C
R12 R18 R19 R58 = R_0402_270_5%_PW: RES 270 OHM 1/5W 5% 0402 SMD; Manufacturer: Rohm Semiconductor; Manufacturer Part Number: ESR01MZPJ271; Temperature Coefficient: ±200ppm/°C
R13 = R_01005_100K: RES 100K OHM 1/32W 1% 01005 SMD; Manufacturer: Yageo; Manufacturer Part Number: RC0100FR-07100KL; Temperature Coefficient: ±250ppm/°C
R14 = R_01005_4.7k: as R27 on sheet FPGA Config
U4 = U_LTC3460-1: IC REG BOOST ADJ 0.18A 6DFN; Output Type: Adjustable; Number of Outputs: 1; PWM Type: Current Mode; Synchronous Rectifier: No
